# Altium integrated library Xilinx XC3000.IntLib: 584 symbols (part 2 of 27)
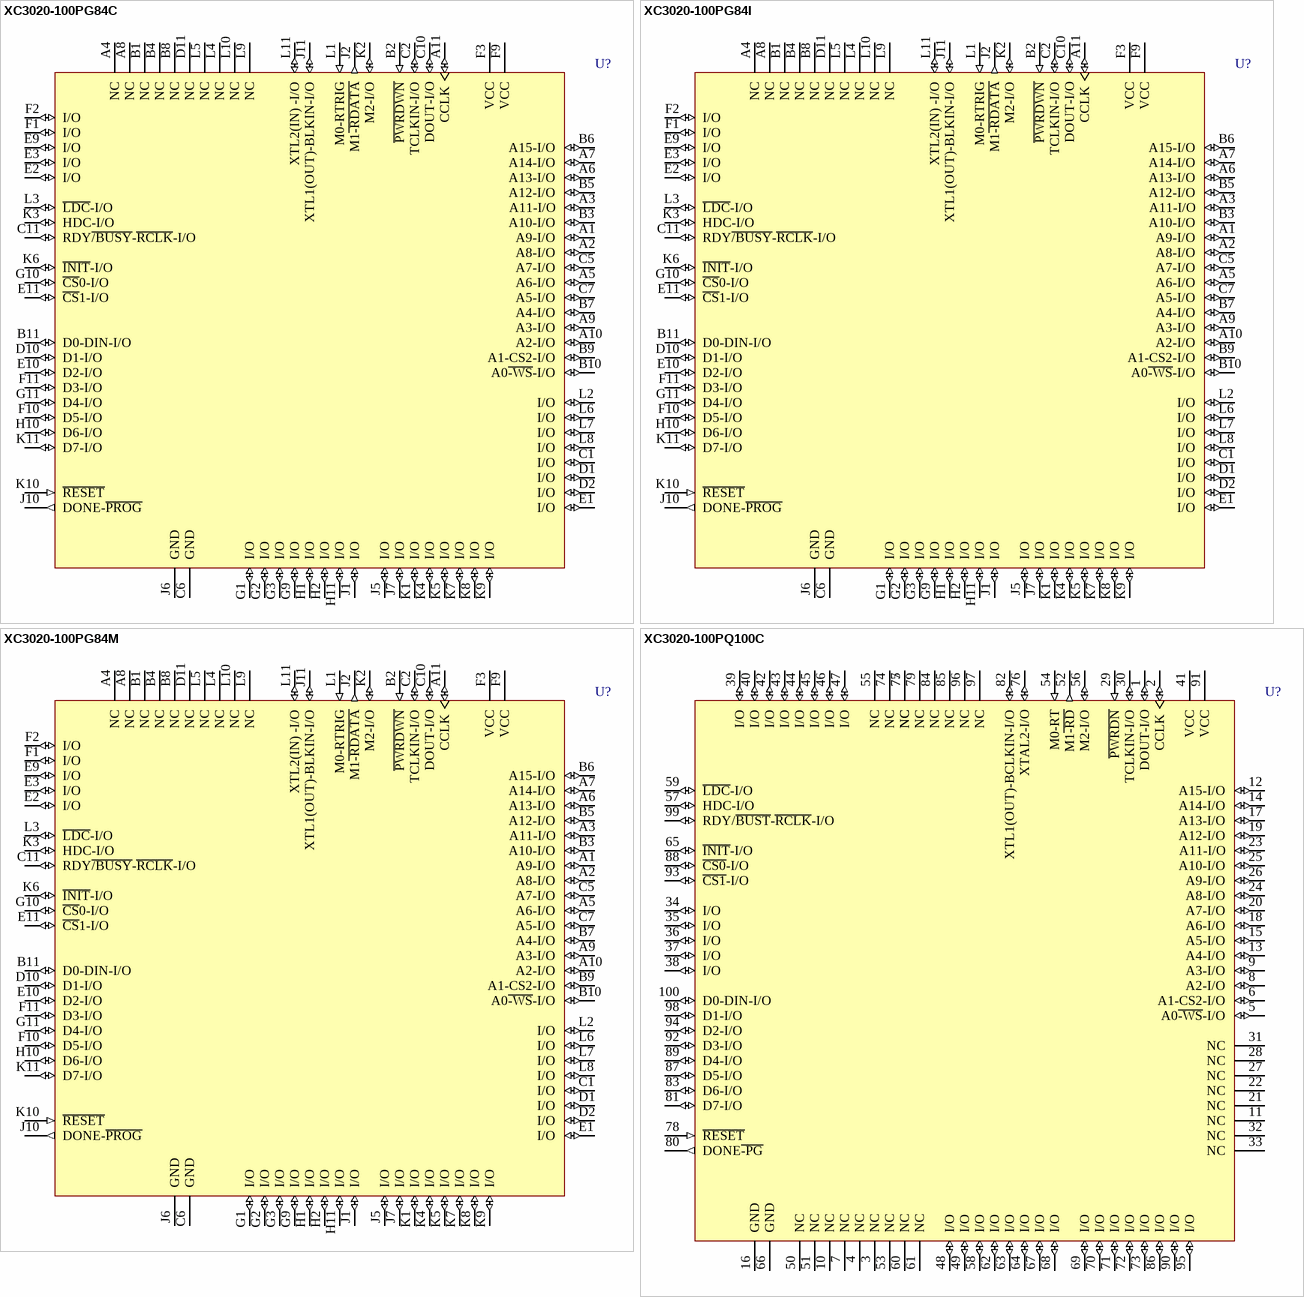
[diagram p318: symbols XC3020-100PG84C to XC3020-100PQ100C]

## XC3020-100PG84C
designator U?
Logic Cell Array with 64 CLBs, with 64 I/O Pins, 84-Pin PGA, Commercial Grade; ComponentAvailability: Not for New Design
footprint PG84 (PGA, 85-Leads, Body 28x28mm, Pitch 2.54mm)
3D model XC3020-PG84 (84-Pin Ceramic Pin Grid Array (PG84))
pins: A1 A9-I/O (io), A2 A8-I/O (io), A3 A11-I/O (io), A4 NC, A5 A6-I/O (io), A6 A13-I/O (io), A7 A14-I/O (io), A8 NC, A9 A3-I/O (io), A10 A2-I/O (io), A11 CCLK (io), B1 NC, B2 ~{PWRDWN} (in), B3 A10-I/O (io), B4 NC, B5 A12-I/O (io), B6 A15-I/O (io), B7 A4-I/O (io), B8 NC, B9 A1-CS2-I/O (io), B10 A0~{-WS}-I/O (io), B11 D0-DIN-I/O (io), C1 I/O (io), C2 TCLKIN-I/O (io), C5 A7-I/O (io), C6 GND (power), C7 A5-I/O (io), C10 DOUT-I/O (io), C11 RDY~{/BUSY}-~{RCLK}-I/O (io), D1 I/O (io), D2 I/O (io), D10 D1-I/O (io), D11 NC, E1 I/O (io), E2 I/O (io), E3 I/O (io), E9 I/O (io), E10 D2-I/O (io), E11 ~{CS}1-I/O (io), F1 I/O (io), F2 I/O (io), F3 VCC (power), F9 VCC (power), F10 D5-I/O (io), F11 D3-I/O (io), G1 I/O (io), G2 I/O (io), G3 I/O (io), G9 I/O (io), G10 ~{CS}0-I/O (io), G11 D4-I/O (io), H1 I/O (io), H2 I/O (io), H10 D6-I/O (io), H11 I/O (io), J1 I/O (io), J2 M1~{-RDATA} (out), J5 I/O (io), J6 GND (power), J7 I/O (io), J10 DONE-~{PROG} (out), J11 XTL1(OUT)-BLKIN-I/O (io), K1 I/O (io), K2 M2-I/O (io), K3 HDC-I/O (io), K4 I/O (io), K5 I/O (io), K6 ~{INIT}-I/O (io), K7 I/O (io), K8 I/O (io), K9 I/O (io), K10 ~{RESET} (in), K11 D7-I/O (io), L1 M0-RTRIG (in), L2 I/O (io), L3 ~{LDC}-I/O (io), L4 NC, L5 NC, L6 I/O (io), L7 I/O (io), L8 I/O (io), L9 NC, L10 NC, L11 XTL2(IN) -I/O (io)

## XC3020-100PG84I
designator U?
Logic Cell Array with 64 CLBs, with 64 I/O Pins, 84-Pin PGA, Industrial Grade; ComponentAvailability: Not for New Design
footprint PG84 (PGA, 85-Leads, Body 28x28mm, Pitch 2.54mm)
3D model XC3020-PG84 (84-Pin Ceramic Pin Grid Array (PG84))
pins: A1 A9-I/O (io), A2 A8-I/O (io), A3 A11-I/O (io), A4 NC, A5 A6-I/O (io), A6 A13-I/O (io), A7 A14-I/O (io), A8 NC, A9 A3-I/O (io), A10 A2-I/O (io), A11 CCLK (io), B1 NC, B2 ~{PWRDWN} (in), B3 A10-I/O (io), B4 NC, B5 A12-I/O (io), B6 A15-I/O (io), B7 A4-I/O (io), B8 NC, B9 A1-CS2-I/O (io), B10 A0~{-WS}-I/O (io), B11 D0-DIN-I/O (io), C1 I/O (io), C2 TCLKIN-I/O (io), C5 A7-I/O (io), C6 GND (power), C7 A5-I/O (io), C10 DOUT-I/O (io), C11 RDY~{/BUSY}-~{RCLK}-I/O (io), D1 I/O (io), D2 I/O (io), D10 D1-I/O (io), D11 NC, E1 I/O (io), E2 I/O (io), E3 I/O (io), E9 I/O (io), E10 D2-I/O (io), E11 ~{CS}1-I/O (io), F1 I/O (io), F2 I/O (io), F3 VCC (power), F9 VCC (power), F10 D5-I/O (io), F11 D3-I/O (io), G1 I/O (io), G2 I/O (io), G3 I/O (io), G9 I/O (io), G10 ~{CS}0-I/O (io), G11 D4-I/O (io), H1 I/O (io), H2 I/O (io), H10 D6-I/O (io), H11 I/O (io), J1 I/O (io), J2 M1~{-RDATA} (out), J5 I/O (io), J6 GND (power), J7 I/O (io), J10 DONE-~{PROG} (out), J11 XTL1(OUT)-BLKIN-I/O (io), K1 I/O (io), K2 M2-I/O (io), K3 HDC-I/O (io), K4 I/O (io), K5 I/O (io), K6 ~{INIT}-I/O (io), K7 I/O (io), K8 I/O (io), K9 I/O (io), K10 ~{RESET} (in), K11 D7-I/O (io), L1 M0-RTRIG (in), L2 I/O (io), L3 ~{LDC}-I/O (io), L4 NC, L5 NC, L6 I/O (io), L7 I/O (io), L8 I/O (io), L9 NC, L10 NC, L11 XTL2(IN) -I/O (io)

## XC3020-100PG84M
designator U?
Logic Cell Array with 64 CLBs, with 64 I/O Pins, 84-Pin PGA, Military Grade; ComponentAvailability: Not for New Design
footprint PG84 (PGA, 85-Leads, Body 28x28mm, Pitch 2.54mm)
3D model XC3020-PG84 (84-Pin Ceramic Pin Grid Array (PG84))
pins: A1 A9-I/O (io), A2 A8-I/O (io), A3 A11-I/O (io), A4 NC, A5 A6-I/O (io), A6 A13-I/O (io), A7 A14-I/O (io), A8 NC, A9 A3-I/O (io), A10 A2-I/O (io), A11 CCLK (io), B1 NC, B2 ~{PWRDWN} (in), B3 A10-I/O (io), B4 NC, B5 A12-I/O (io), B6 A15-I/O (io), B7 A4-I/O (io), B8 NC, B9 A1-CS2-I/O (io), B10 A0~{-WS}-I/O (io), B11 D0-DIN-I/O (io), C1 I/O (io), C2 TCLKIN-I/O (io), C5 A7-I/O (io), C6 GND (power), C7 A5-I/O (io), C10 DOUT-I/O (io), C11 RDY~{/BUSY}-~{RCLK}-I/O (io), D1 I/O (io), D2 I/O (io), D10 D1-I/O (io), D11 NC, E1 I/O (io), E2 I/O (io), E3 I/O (io), E9 I/O (io), E10 D2-I/O (io), E11 ~{CS}1-I/O (io), F1 I/O (io), F2 I/O (io), F3 VCC (power), F9 VCC (power), F10 D5-I/O (io), F11 D3-I/O (io), G1 I/O (io), G2 I/O (io), G3 I/O (io), G9 I/O (io), G10 ~{CS}0-I/O (io), G11 D4-I/O (io), H1 I/O (io), H2 I/O (io), H10 D6-I/O (io), H11 I/O (io), J1 I/O (io), J2 M1~{-RDATA} (out), J5 I/O (io), J6 GND (power), J7 I/O (io), J10 DONE-~{PROG} (out), J11 XTL1(OUT)-BLKIN-I/O (io), K1 I/O (io), K2 M2-I/O (io), K3 HDC-I/O (io), K4 I/O (io), K5 I/O (io), K6 ~{INIT}-I/O (io), K7 I/O (io), K8 I/O (io), K9 I/O (io), K10 ~{RESET} (in), K11 D7-I/O (io), L1 M0-RTRIG (in), L2 I/O (io), L3 ~{LDC}-I/O (io), L4 NC, L5 NC, L6 I/O (io), L7 I/O (io), L8 I/O (io), L9 NC, L10 NC, L11 XTL2(IN) -I/O (io)

## XC3020-100PQ100C
designator U?
Logic Cell Array with 64 CLBs, with 64 I/O Pins, 100-Pin PQFP, Commercial Grade; ComponentAvailability: Not for New Design
footprint PQ100_N (QFP, 100-Leads, Body 20x14mm, Pitch 0.65mm, IPC Medium Density)
footprint PQ100_L (QFP, 100-Leads, Body 20x14mm, Pitch 0.65mm, IPC High Density)
footprint PQ100_M (QFP, 100-Leads, Body 20x14mm, Pitch 0.65mm, IPC Low Density)
3D model XC3020-PQ100 (100-Pin Plastic Quad Flat Pack (PQ100))
pins: 1 DOUT-I/O (io), 2 CCLK (io), 3 NC, 4 NC, 5 A0~{-WS}-I/O (io), 6 A1-CS2-I/O (io), 7 NC, 8 A2-I/O (io), 9 A3-I/O (io), 10 NC, 11 NC, 12 A15-I/O (io), 13 A4-I/O (io), 14 A14-I/O (io), 15 A5-I/O (io), 16 GND (power), 17 A13-I/O (io), 18 A6-I/O (io), 19 A12-I/O (io), 20 A7-I/O (io), 21 NC, 22 NC, 23 A11-I/O (io), 24 A8-I/O (io), 25 A10-I/O (io), 26 A9-I/O (io), 27 NC, 28 NC, 29 ~{PWRDN} (in), 30 TCLKIN-I/O (io), 31 NC, 32 NC, 33 NC, 34 I/O (io), 35 I/O (io), 36 I/O (io), 37 I/O (io), 38 I/O (io), 39 I/O (io), 40 I/O (io), 41 VCC (power), 42 I/O (io), 43 I/O (io), 44 I/O (io), 45 I/O (io), 46 I/O (io), 47 I/O (io), 48 I/O (io), 49 I/O (io), 50 NC, 51 NC, 52 M1~{-RD} (out), 53 NC, 54 M0-RT (in), 55 NC, 56 M2-I/O (io), 57 HDC-I/O (io), 58 I/O (io), 59 ~{LDC}-I/O (io), 60 NC, 61 NC, 62 I/O (io), 63 I/O (io), 64 I/O (io), 65 ~{INIT}-I/O (io), 66 GND (power), 67 I/O (io), 68 I/O (io), 69 I/O (io), 70 I/O (io), 71 I/O (io), 72 I/O (io), 73 I/O (io), 74 NC, 75 NC, 76 XTAL2-I/O (io), 77 NC, 78 ~{RESET} (in), 79 NC, 80 DONE~{-PG} (out), 81 D7-I/O (io), 82 XTL1(OUT)-BCLKIN-I/O (io), 83 D6-I/O (io), 84 NC, 85 NC, 86 I/O (io), 87 D5-I/O (io), 88 ~{CS0}-I/O (io), 89 D4-I/O (io), 90 I/O (io), 91 VCC (power), 92 D3-I/O (io), 93 ~{CS1}-I/O (io), 94 D2-I/O (io), 95 I/O (io), 96 NC, 97 NC, 98 D1-I/O (io), 99 RDY/~{BUST}-~{RCLK}-I/O (io), 100 D0-DIN-I/O (io)

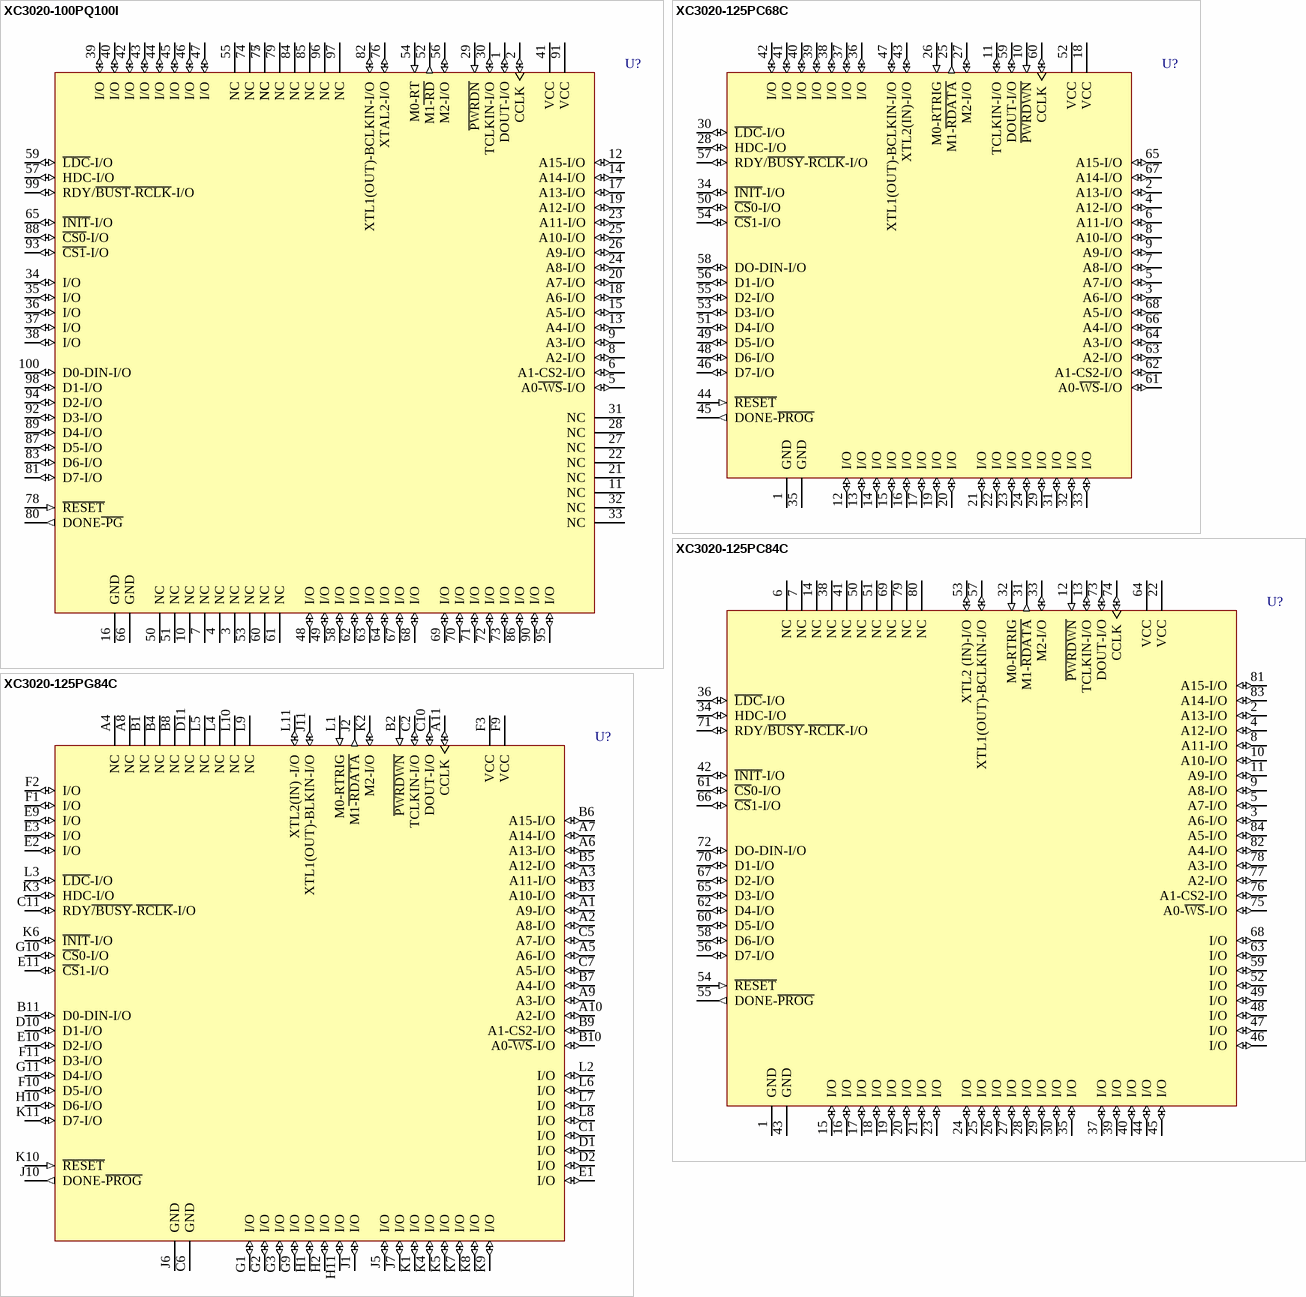
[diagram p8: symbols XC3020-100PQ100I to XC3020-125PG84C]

## XC3020-100PQ100I
designator U?
Logic Cell Array with 64 CLBs, with 64 I/O Pins, 100-Pin PQFP, Industrial Grade; ComponentAvailability: Not for New Design
footprint PQ100_N (QFP, 100-Leads, Body 20x14mm, Pitch 0.65mm, IPC Medium Density)
footprint PQ100_L (QFP, 100-Leads, Body 20x14mm, Pitch 0.65mm, IPC High Density)
footprint PQ100_M (QFP, 100-Leads, Body 20x14mm, Pitch 0.65mm, IPC Low Density)
3D model XC3020-PQ100 (100-Pin Plastic Quad Flat Pack (PQ100))
pins: 1 DOUT-I/O (io), 2 CCLK (io), 3 NC, 4 NC, 5 A0~{-WS}-I/O (io), 6 A1-CS2-I/O (io), 7 NC, 8 A2-I/O (io), 9 A3-I/O (io), 10 NC, 11 NC, 12 A15-I/O (io), 13 A4-I/O (io), 14 A14-I/O (io), 15 A5-I/O (io), 16 GND (power), 17 A13-I/O (io), 18 A6-I/O (io), 19 A12-I/O (io), 20 A7-I/O (io), 21 NC, 22 NC, 23 A11-I/O (io), 24 A8-I/O (io), 25 A10-I/O (io), 26 A9-I/O (io), 27 NC, 28 NC, 29 ~{PWRDN} (in), 30 TCLKIN-I/O (io), 31 NC, 32 NC, 33 NC, 34 I/O (io), 35 I/O (io), 36 I/O (io), 37 I/O (io), 38 I/O (io), 39 I/O (io), 40 I/O (io), 41 VCC (power), 42 I/O (io), 43 I/O (io), 44 I/O (io), 45 I/O (io), 46 I/O (io), 47 I/O (io), 48 I/O (io), 49 I/O (io), 50 NC, 51 NC, 52 M1~{-RD} (out), 53 NC, 54 M0-RT (in), 55 NC, 56 M2-I/O (io), 57 HDC-I/O (io), 58 I/O (io), 59 ~{LDC}-I/O (io), 60 NC, 61 NC, 62 I/O (io), 63 I/O (io), 64 I/O (io), 65 ~{INIT}-I/O (io), 66 GND (power), 67 I/O (io), 68 I/O (io), 69 I/O (io), 70 I/O (io), 71 I/O (io), 72 I/O (io), 73 I/O (io), 74 NC, 75 NC, 76 XTAL2-I/O (io), 77 NC, 78 ~{RESET} (in), 79 NC, 80 DONE~{-PG} (out), 81 D7-I/O (io), 82 XTL1(OUT)-BCLKIN-I/O (io), 83 D6-I/O (io), 84 NC, 85 NC, 86 I/O (io), 87 D5-I/O (io), 88 ~{CS0}-I/O (io), 89 D4-I/O (io), 90 I/O (io), 91 VCC (power), 92 D3-I/O (io), 93 ~{CS1}-I/O (io), 94 D2-I/O (io), 95 I/O (io), 96 NC, 97 NC, 98 D1-I/O (io), 99 RDY/~{BUST}-~{RCLK}-I/O (io), 100 D0-DIN-I/O (io)

## XC3020-125PC68C
designator U?
Logic Cell Array with 64 CLBs, with 58 I/O Pins, 68-Pin PLCC, Commercial Grade; ComponentAvailability: Not for New Design
footprint PC68_N (Leaded Chip Carrier, 68-Leads, Body 24x24mm, Pitch 1.27mm, IPC Medium Density)
footprint PC68_L (Leaded Chip Carrier, 68-Leads, Body 24x24mm, Pitch 1.27mm, IPC High Density)
footprint PC68_M (Leaded Chip Carrier, 68-Leads, Body 24x24mm, Pitch 1.27mm, IPC Low Density)
3D model XC3020-PC68 (68-Pin Plastic Leaded Chip Carrier (PC68))
pins: 1 GND (power), 2 A13-I/O (io), 3 A6-I/O (io), 4 A12-I/O (io), 5 A7-I/O (io), 6 A11-I/O (io), 7 A8-I/O (io), 8 A10-I/O (io), 9 A9-I/O (io), 10 ~{PWRDWN} (in), 11 TCLKIN-I/O (io), 12 I/O (io), 13 I/O (io), 14 I/O (io), 15 I/O (io), 16 I/O (io), 17 I/O (io), 18 VCC (power), 19 I/O (io), 20 I/O (io), 21 I/O (io), 22 I/O (io), 23 I/O (io), 24 I/O (io), 25 M1-~{RDATA} (out), 26 M0-RTRIG (in), 27 M2-I/O (io), 28 HDC-I/O (io), 29 I/O (io), 30 ~{LDC}-I/O (io), 31 I/O (io), 32 I/O (io), 33 I/O (io), 34 ~{INIT}-I/O (io), 35 GND (power), 36 I/O (io), 37 I/O (io), 38 I/O (io), 39 I/O (io), 40 I/O (io), 41 I/O (io), 42 I/O (io), 43 XTL2(IN)-I/O (io), 44 ~{RESET} (in), 45 DONE-~{PROG} (out), 46 D7-I/O (io), 47 XTL1(OUT)-BCLKIN-I/O (io), 48 D6-I/O (io), 49 D5-I/O (io), 50 ~{CS}0-I/O (io), 51 D4-I/O (io), 52 VCC (power), 53 D3-I/O (io), 54 ~{CS}1-I/O (io), 55 D2-I/O (io), 56 D1-I/O (io), 57 RDY/~{BUSY}-~{RCLK}-I/O (io), 58 DO-DIN-I/O (io), 59 DOUT-I/O (io), 60 CCLK (io), 61 A0-~{WS}-I/O (io), 62 A1-CS2-I/O (io), 63 A2-I/O (io), 64 A3-I/O (io), 65 A15-I/O (io), 66 A4-I/O (io), 67 A14-I/O (io), 68 A5-I/O (io)

## XC3020-125PC84C
designator U?
Logic Cell Array with 64 CLBs, with 64 I/O Pins, 84-Pin PLCC, Commercial Grade; ComponentAvailability: Not for New Design
footprint PC84_N (Leaded Chip Carrier, 84-Leads, Body 29.3x29.3mm, Pitch 1.27mm, IPC Medium Density)
footprint PC84_L (Leaded Chip Carrier, 84-Leads, Body 29.3x29.3mm, Pitch 1.27mm, IPC High Density)
footprint PC84_M (Leaded Chip Carrier, 84-Leads, Body 29.3x29.3mm, Pitch 1.27mm, IPC Low Density)
3D model XC3020-PC84 (84-Pin Plastic Leaded Chip Carrier (PC84))
pins: 1 GND (power), 2 A13-I/O (io), 3 A6-I/O (io), 4 A12-I/O (io), 5 A7-I/O (io), 6 NC, 7 NC, 8 A11-I/O (io), 9 A8-I/O (io), 10 A10-I/O (io), 11 A9-I/O (io), 12 ~{PWRDWN} (in), 13 TCLKIN-I/O (io), 14 NC, 15 I/O (io), 16 I/O (io), 17 I/O (io), 18 I/O (io), 19 I/O (io), 20 I/O (io), 21 I/O (io), 22 VCC (power), 23 I/O (io), 24 I/O (io), 25 I/O (io), 26 I/O (io), 27 I/O (io), 28 I/O (io), 29 I/O (io), 30 I/O (io), 31 M1-~{RDATA} (out), 32 M0-RTRIG (in), 33 M2-I/O (io), 34 HDC-I/O (io), 35 I/O (io), 36 ~{LDC}-I/O (io), 37 I/O (io), 38 NC, 39 I/O (io), 40 I/O (io), 41 NC, 42 ~{INIT}-I/O (io), 43 GND (power), 44 I/O (io), 45 I/O (io), 46 I/O (io), 47 I/O (io), 48 I/O (io), 49 I/O (io), 50 NC, 51 NC, 52 I/O (io), 53 XTL2 (IN)-I/O (io), 54 ~{RESET} (in), 55 DONE-~{PROG} (out), 56 D7-I/O (io), 57 XTL1(OUT)-BCLKIN-I/O (io), 58 D6-I/O (io), 59 I/O (io), 60 D5-I/O (io), 61 ~{CS}0-I/O (io), 62 D4-I/O (io), 63 I/O (io), 64 VCC (power), 65 D3-I/O (io), 66 ~{CS}1-I/O (io), 67 D2-I/O (io), 68 I/O (io), 69 NC, 70 D1-I/O (io), 71 RDY/~{BUSY}-~{RCLK}-I/O (io), 72 DO-DIN-I/O (io), 73 DOUT-I/O (io), 74 CCLK (io), 75 A0-~{WS}-I/O (io), 76 A1-CS2-I/O (io), 77 A2-I/O (io), 78 A3-I/O (io), 79 NC, 80 NC, 81 A15-I/O (io), 82 A4-I/O (io), 83 A14-I/O (io), 84 A5-I/O (io)

## XC3020-125PG84C
designator U?
Logic Cell Array with 64 CLBs, with 64 I/O Pins, 84-Pin PGA, Commercial Grade; ComponentAvailability: Not for New Design
footprint PG84 (PGA, 85-Leads, Body 28x28mm, Pitch 2.54mm)
3D model XC3020-PG84 (84-Pin Ceramic Pin Grid Array (PG84))
pins: A1 A9-I/O (io), A2 A8-I/O (io), A3 A11-I/O (io), A4 NC, A5 A6-I/O (io), A6 A13-I/O (io), A7 A14-I/O (io), A8 NC, A9 A3-I/O (io), A10 A2-I/O (io), A11 CCLK (io), B1 NC, B2 ~{PWRDWN} (in), B3 A10-I/O (io), B4 NC, B5 A12-I/O (io), B6 A15-I/O (io), B7 A4-I/O (io), B8 NC, B9 A1-CS2-I/O (io), B10 A0~{-WS}-I/O (io), B11 D0-DIN-I/O (io), C1 I/O (io), C2 TCLKIN-I/O (io), C5 A7-I/O (io), C6 GND (power), C7 A5-I/O (io), C10 DOUT-I/O (io), C11 RDY~{/BUSY}-~{RCLK}-I/O (io), D1 I/O (io), D2 I/O (io), D10 D1-I/O (io), D11 NC, E1 I/O (io), E2 I/O (io), E3 I/O (io), E9 I/O (io), E10 D2-I/O (io), E11 ~{CS}1-I/O (io), F1 I/O (io), F2 I/O (io), F3 VCC (power), F9 VCC (power), F10 D5-I/O (io), F11 D3-I/O (io), G1 I/O (io), G2 I/O (io), G3 I/O (io), G9 I/O (io), G10 ~{CS}0-I/O (io), G11 D4-I/O (io), H1 I/O (io), H2 I/O (io), H10 D6-I/O (io), H11 I/O (io), J1 I/O (io), J2 M1~{-RDATA} (out), J5 I/O (io), J6 GND (power), J7 I/O (io), J10 DONE-~{PROG} (out), J11 XTL1(OUT)-BLKIN-I/O (io), K1 I/O (io), K2 M2-I/O (io), K3 HDC-I/O (io), K4 I/O (io), K5 I/O (io), K6 ~{INIT}-I/O (io), K7 I/O (io), K8 I/O (io), K9 I/O (io), K10 ~{RESET} (in), K11 D7-I/O (io), L1 M0-RTRIG (in), L2 I/O (io), L3 ~{LDC}-I/O (io), L4 NC, L5 NC, L6 I/O (io), L7 I/O (io), L8 I/O (io), L9 NC, L10 NC, L11 XTL2(IN) -I/O (io)

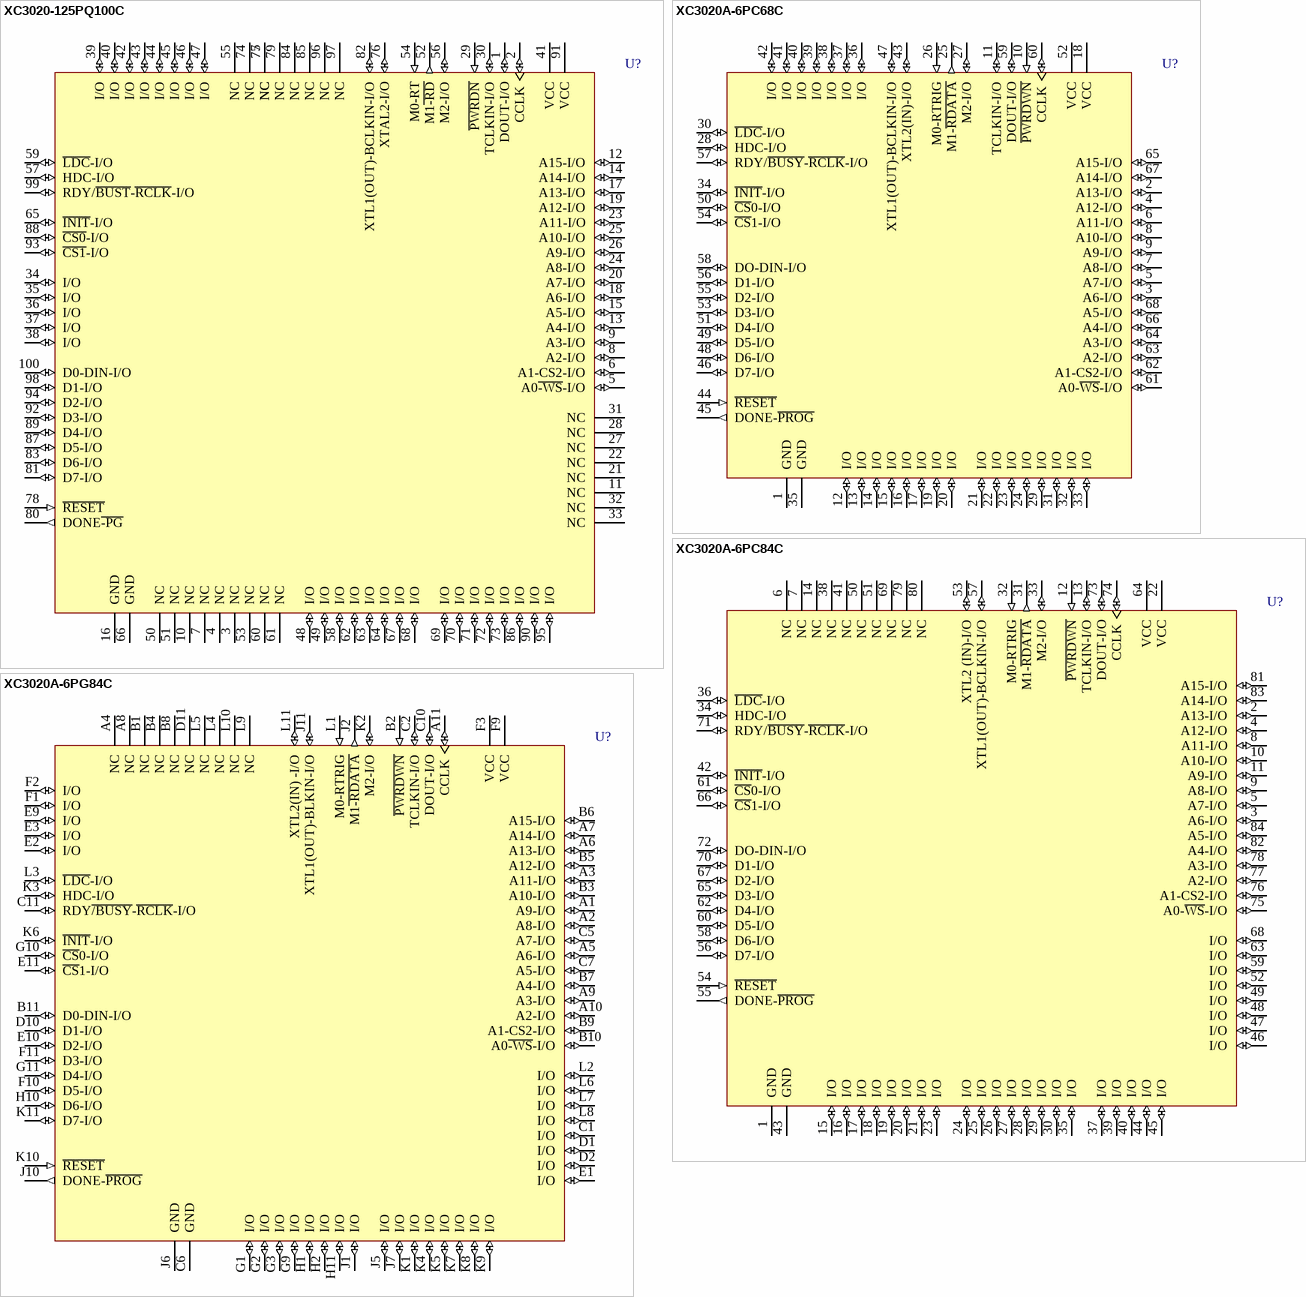
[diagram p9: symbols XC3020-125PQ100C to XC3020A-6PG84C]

## XC3020-125PQ100C
designator U?
Logic Cell Array with 64 CLBs, with 64 I/O Pins, 100-Pin PQFP, Commercial Grade; ComponentAvailability: Not for New Design
footprint PQ100_N (QFP, 100-Leads, Body 20x14mm, Pitch 0.65mm, IPC Medium Density)
footprint PQ100_L (QFP, 100-Leads, Body 20x14mm, Pitch 0.65mm, IPC High Density)
footprint PQ100_M (QFP, 100-Leads, Body 20x14mm, Pitch 0.65mm, IPC Low Density)
3D model XC3020-PQ100 (100-Pin Plastic Quad Flat Pack (PQ100))
pins: 1 DOUT-I/O (io), 2 CCLK (io), 3 NC, 4 NC, 5 A0~{-WS}-I/O (io), 6 A1-CS2-I/O (io), 7 NC, 8 A2-I/O (io), 9 A3-I/O (io), 10 NC, 11 NC, 12 A15-I/O (io), 13 A4-I/O (io), 14 A14-I/O (io), 15 A5-I/O (io), 16 GND (power), 17 A13-I/O (io), 18 A6-I/O (io), 19 A12-I/O (io), 20 A7-I/O (io), 21 NC, 22 NC, 23 A11-I/O (io), 24 A8-I/O (io), 25 A10-I/O (io), 26 A9-I/O (io), 27 NC, 28 NC, 29 ~{PWRDN} (in), 30 TCLKIN-I/O (io), 31 NC, 32 NC, 33 NC, 34 I/O (io), 35 I/O (io), 36 I/O (io), 37 I/O (io), 38 I/O (io), 39 I/O (io), 40 I/O (io), 41 VCC (power), 42 I/O (io), 43 I/O (io), 44 I/O (io), 45 I/O (io), 46 I/O (io), 47 I/O (io), 48 I/O (io), 49 I/O (io), 50 NC, 51 NC, 52 M1~{-RD} (out), 53 NC, 54 M0-RT (in), 55 NC, 56 M2-I/O (io), 57 HDC-I/O (io), 58 I/O (io), 59 ~{LDC}-I/O (io), 60 NC, 61 NC, 62 I/O (io), 63 I/O (io), 64 I/O (io), 65 ~{INIT}-I/O (io), 66 GND (power), 67 I/O (io), 68 I/O (io), 69 I/O (io), 70 I/O (io), 71 I/O (io), 72 I/O (io), 73 I/O (io), 74 NC, 75 NC, 76 XTAL2-I/O (io), 77 NC, 78 ~{RESET} (in), 79 NC, 80 DONE~{-PG} (out), 81 D7-I/O (io), 82 XTL1(OUT)-BCLKIN-I/O (io), 83 D6-I/O (io), 84 NC, 85 NC, 86 I/O (io), 87 D5-I/O (io), 88 ~{CS0}-I/O (io), 89 D4-I/O (io), 90 I/O (io), 91 VCC (power), 92 D3-I/O (io), 93 ~{CS1}-I/O (io), 94 D2-I/O (io), 95 I/O (io), 96 NC, 97 NC, 98 D1-I/O (io), 99 RDY/~{BUST}-~{RCLK}-I/O (io), 100 D0-DIN-I/O (io)

## XC3020A-6PC68C
designator U?
Logic Cell Array with 64 CLBs, with 58 I/O Pins, 68-Pin PLCC, Commercial Grade; ComponentAvailability: Not for New Design
footprint PC68_N (Leaded Chip Carrier, 68-Leads, Body 24x24mm, Pitch 1.27mm, IPC Medium Density)
footprint PC68_L (Leaded Chip Carrier, 68-Leads, Body 24x24mm, Pitch 1.27mm, IPC High Density)
footprint PC68_M (Leaded Chip Carrier, 68-Leads, Body 24x24mm, Pitch 1.27mm, IPC Low Density)
3D model XC3020A-PC68 (68-Pin Plastic Leaded Chip Carrier (PC68))
pins: 1 GND (power), 2 A13-I/O (io), 3 A6-I/O (io), 4 A12-I/O (io), 5 A7-I/O (io), 6 A11-I/O (io), 7 A8-I/O (io), 8 A10-I/O (io), 9 A9-I/O (io), 10 ~{PWRDWN} (in), 11 TCLKIN-I/O (io), 12 I/O (io), 13 I/O (io), 14 I/O (io), 15 I/O (io), 16 I/O (io), 17 I/O (io), 18 VCC (power), 19 I/O (io), 20 I/O (io), 21 I/O (io), 22 I/O (io), 23 I/O (io), 24 I/O (io), 25 M1-~{RDATA} (out), 26 M0-RTRIG (in), 27 M2-I/O (io), 28 HDC-I/O (io), 29 I/O (io), 30 ~{LDC}-I/O (io), 31 I/O (io), 32 I/O (io), 33 I/O (io), 34 ~{INIT}-I/O (io), 35 GND (power), 36 I/O (io), 37 I/O (io), 38 I/O (io), 39 I/O (io), 40 I/O (io), 41 I/O (io), 42 I/O (io), 43 XTL2(IN)-I/O (io), 44 ~{RESET} (in), 45 DONE-~{PROG} (out), 46 D7-I/O (io), 47 XTL1(OUT)-BCLKIN-I/O (io), 48 D6-I/O (io), 49 D5-I/O (io), 50 ~{CS}0-I/O (io), 51 D4-I/O (io), 52 VCC (power), 53 D3-I/O (io), 54 ~{CS}1-I/O (io), 55 D2-I/O (io), 56 D1-I/O (io), 57 RDY/~{BUSY}-~{RCLK}-I/O (io), 58 DO-DIN-I/O (io), 59 DOUT-I/O (io), 60 CCLK (io), 61 A0-~{WS}-I/O (io), 62 A1-CS2-I/O (io), 63 A2-I/O (io), 64 A3-I/O (io), 65 A15-I/O (io), 66 A4-I/O (io), 67 A14-I/O (io), 68 A5-I/O (io)

## XC3020A-6PC84C
designator U?
Logic Cell Array with 64 CLBs, with 64 I/O Pins, 84-Pin PLCC, Commercial Grade; ComponentAvailability: Not for New Design
footprint PC84_N (Leaded Chip Carrier, 84-Leads, Body 29.3x29.3mm, Pitch 1.27mm, IPC Medium Density)
footprint PC84_L (Leaded Chip Carrier, 84-Leads, Body 29.3x29.3mm, Pitch 1.27mm, IPC High Density)
footprint PC84_M (Leaded Chip Carrier, 84-Leads, Body 29.3x29.3mm, Pitch 1.27mm, IPC Low Density)
3D model XC3020A-PC84 (84-Pin Plastic Leaded Chip Carrier (PC84))
pins: 1 GND (power), 2 A13-I/O (io), 3 A6-I/O (io), 4 A12-I/O (io), 5 A7-I/O (io), 6 NC, 7 NC, 8 A11-I/O (io), 9 A8-I/O (io), 10 A10-I/O (io), 11 A9-I/O (io), 12 ~{PWRDWN} (in), 13 TCLKIN-I/O (io), 14 NC, 15 I/O (io), 16 I/O (io), 17 I/O (io), 18 I/O (io), 19 I/O (io), 20 I/O (io), 21 I/O (io), 22 VCC (power), 23 I/O (io), 24 I/O (io), 25 I/O (io), 26 I/O (io), 27 I/O (io), 28 I/O (io), 29 I/O (io), 30 I/O (io), 31 M1-~{RDATA} (out), 32 M0-RTRIG (in), 33 M2-I/O (io), 34 HDC-I/O (io), 35 I/O (io), 36 ~{LDC}-I/O (io), 37 I/O (io), 38 NC, 39 I/O (io), 40 I/O (io), 41 NC, 42 ~{INIT}-I/O (io), 43 GND (power), 44 I/O (io), 45 I/O (io), 46 I/O (io), 47 I/O (io), 48 I/O (io), 49 I/O (io), 50 NC, 51 NC, 52 I/O (io), 53 XTL2 (IN)-I/O (io), 54 ~{RESET} (in), 55 DONE-~{PROG} (out), 56 D7-I/O (io), 57 XTL1(OUT)-BCLKIN-I/O (io), 58 D6-I/O (io), 59 I/O (io), 60 D5-I/O (io), 61 ~{CS}0-I/O (io), 62 D4-I/O (io), 63 I/O (io), 64 VCC (power), 65 D3-I/O (io), 66 ~{CS}1-I/O (io), 67 D2-I/O (io), 68 I/O (io), 69 NC, 70 D1-I/O (io), 71 RDY/~{BUSY}-~{RCLK}-I/O (io), 72 DO-DIN-I/O (io), 73 DOUT-I/O (io), 74 CCLK (io), 75 A0-~{WS}-I/O (io), 76 A1-CS2-I/O (io), 77 A2-I/O (io), 78 A3-I/O (io), 79 NC, 80 NC, 81 A15-I/O (io), 82 A4-I/O (io), 83 A14-I/O (io), 84 A5-I/O (io)

## XC3020A-6PG84C
designator U?
Logic Cell Array with 64 CLBs, with 64 I/O Pins, 84-Pin PGA, Commercial Grade; ComponentAvailability: Not for New Design
footprint PG84 (PGA, 85-Leads, Body 28x28mm, Pitch 2.54mm)
3D model XC3020A-PG84 (84-Pin Ceramic Pin Grid Array (PG84))
pins: A1 A9-I/O (io), A2 A8-I/O (io), A3 A11-I/O (io), A4 NC, A5 A6-I/O (io), A6 A13-I/O (io), A7 A14-I/O (io), A8 NC, A9 A3-I/O (io), A10 A2-I/O (io), A11 CCLK (io), B1 NC, B2 ~{PWRDWN} (in), B3 A10-I/O (io), B4 NC, B5 A12-I/O (io), B6 A15-I/O (io), B7 A4-I/O (io), B8 NC, B9 A1-CS2-I/O (io), B10 A0~{-WS}-I/O (io), B11 D0-DIN-I/O (io), C1 I/O (io), C2 TCLKIN-I/O (io), C5 A7-I/O (io), C6 GND (power), C7 A5-I/O (io), C10 DOUT-I/O (io), C11 RDY~{/BUSY}-~{RCLK}-I/O (io), D1 I/O (io), D2 I/O (io), D10 D1-I/O (io), D11 NC, E1 I/O (io), E2 I/O (io), E3 I/O (io), E9 I/O (io), E10 D2-I/O (io), E11 ~{CS}1-I/O (io), F1 I/O (io), F2 I/O (io), F3 VCC (power), F9 VCC (power), F10 D5-I/O (io), F11 D3-I/O (io), G1 I/O (io), G2 I/O (io), G3 I/O (io), G9 I/O (io), G10 ~{CS}0-I/O (io), G11 D4-I/O (io), H1 I/O (io), H2 I/O (io), H10 D6-I/O (io), H11 I/O (io), J1 I/O (io), J2 M1~{-RDATA} (out), J5 I/O (io), J6 GND (power), J7 I/O (io), J10 DONE-~{PROG} (out), J11 XTL1(OUT)-BLKIN-I/O (io), K1 I/O (io), K2 M2-I/O (io), K3 HDC-I/O (io), K4 I/O (io), K5 I/O (io), K6 ~{INIT}-I/O (io), K7 I/O (io), K8 I/O (io), K9 I/O (io), K10 ~{RESET} (in), K11 D7-I/O (io), L1 M0-RTRIG (in), L2 I/O (io), L3 ~{LDC}-I/O (io), L4 NC, L5 NC, L6 I/O (io), L7 I/O (io), L8 I/O (io), L9 NC, L10 NC, L11 XTL2(IN) -I/O (io)

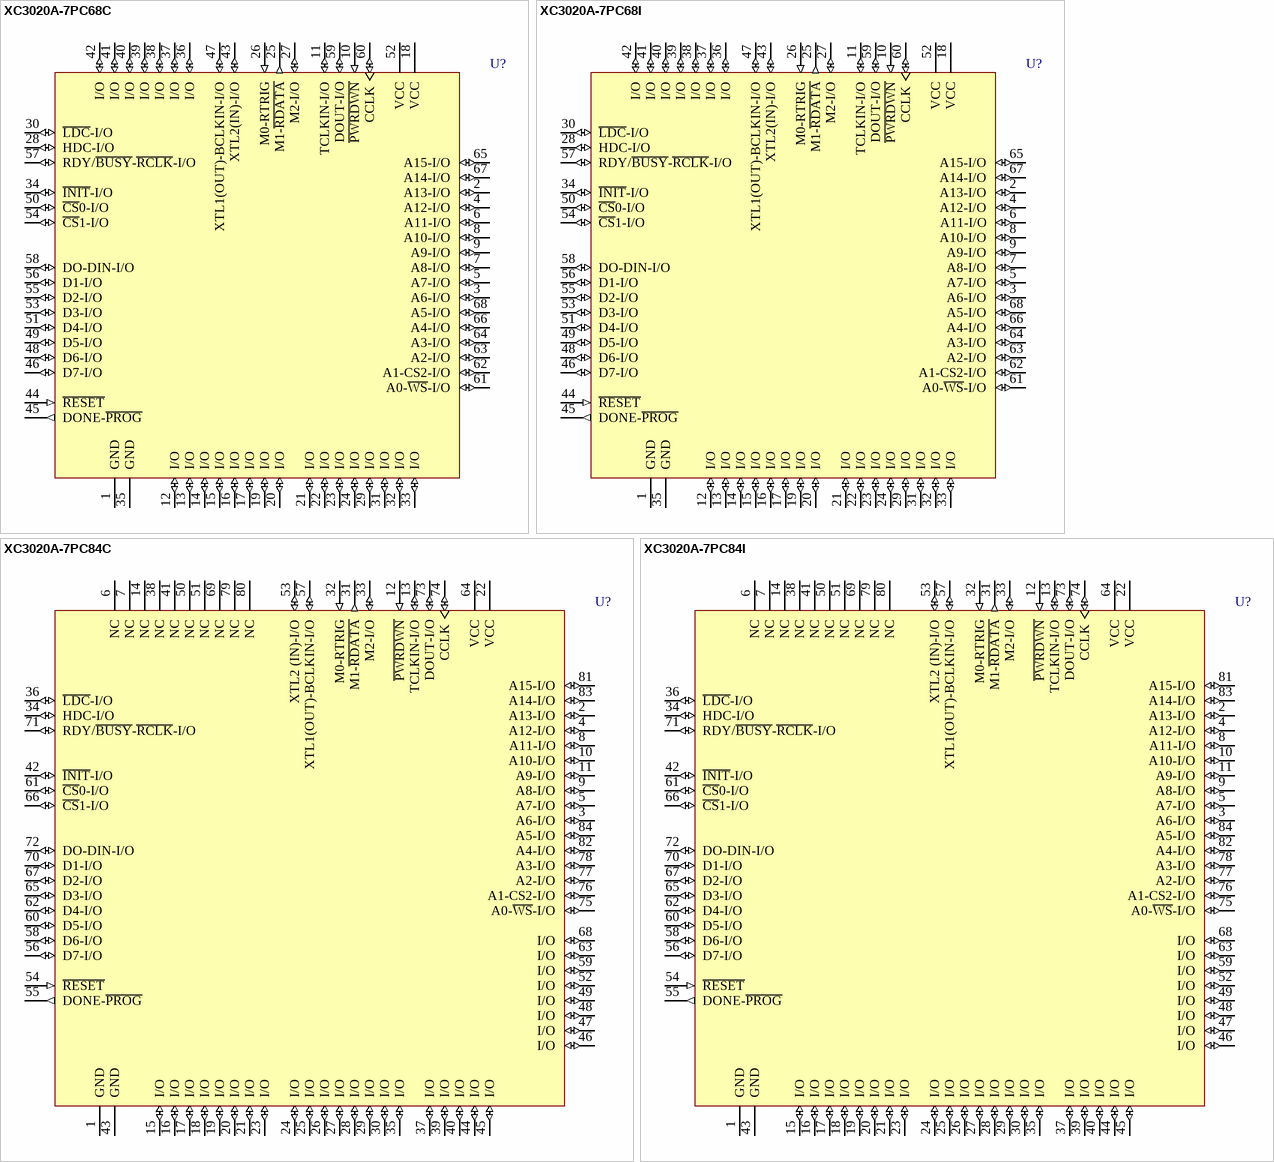
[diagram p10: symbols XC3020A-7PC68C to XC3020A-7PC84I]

## XC3020A-7PC68C
designator U?
Logic Cell Array with 64 CLBs, with 58 I/O Pins, 68-Pin PLCC, Commercial Grade; ComponentAvailability: Not for New Design
footprint PC68_N (Leaded Chip Carrier, 68-Leads, Body 24x24mm, Pitch 1.27mm, IPC Medium Density)
footprint PC68_L (Leaded Chip Carrier, 68-Leads, Body 24x24mm, Pitch 1.27mm, IPC High Density)
footprint PC68_M (Leaded Chip Carrier, 68-Leads, Body 24x24mm, Pitch 1.27mm, IPC Low Density)
3D model XC3020A-PC68 (68-Pin Plastic Leaded Chip Carrier (PC68))
pins: 1 GND (power), 2 A13-I/O (io), 3 A6-I/O (io), 4 A12-I/O (io), 5 A7-I/O (io), 6 A11-I/O (io), 7 A8-I/O (io), 8 A10-I/O (io), 9 A9-I/O (io), 10 ~{PWRDWN} (in), 11 TCLKIN-I/O (io), 12 I/O (io), 13 I/O (io), 14 I/O (io), 15 I/O (io), 16 I/O (io), 17 I/O (io), 18 VCC (power), 19 I/O (io), 20 I/O (io), 21 I/O (io), 22 I/O (io), 23 I/O (io), 24 I/O (io), 25 M1-~{RDATA} (out), 26 M0-RTRIG (in), 27 M2-I/O (io), 28 HDC-I/O (io), 29 I/O (io), 30 ~{LDC}-I/O (io), 31 I/O (io), 32 I/O (io), 33 I/O (io), 34 ~{INIT}-I/O (io), 35 GND (power), 36 I/O (io), 37 I/O (io), 38 I/O (io), 39 I/O (io), 40 I/O (io), 41 I/O (io), 42 I/O (io), 43 XTL2(IN)-I/O (io), 44 ~{RESET} (in), 45 DONE-~{PROG} (out), 46 D7-I/O (io), 47 XTL1(OUT)-BCLKIN-I/O (io), 48 D6-I/O (io), 49 D5-I/O (io), 50 ~{CS}0-I/O (io), 51 D4-I/O (io), 52 VCC (power), 53 D3-I/O (io), 54 ~{CS}1-I/O (io), 55 D2-I/O (io), 56 D1-I/O (io), 57 RDY/~{BUSY}-~{RCLK}-I/O (io), 58 DO-DIN-I/O (io), 59 DOUT-I/O (io), 60 CCLK (io), 61 A0-~{WS}-I/O (io), 62 A1-CS2-I/O (io), 63 A2-I/O (io), 64 A3-I/O (io), 65 A15-I/O (io), 66 A4-I/O (io), 67 A14-I/O (io), 68 A5-I/O (io)

## XC3020A-7PC68I
designator U?
Logic Cell Array with 64 CLBs, with 58 I/O Pins, 68-Pin PLCC, Industrial Grade; ComponentAvailability: Not for New Design
footprint PC68_N (Leaded Chip Carrier, 68-Leads, Body 24x24mm, Pitch 1.27mm, IPC Medium Density)
footprint PC68_L (Leaded Chip Carrier, 68-Leads, Body 24x24mm, Pitch 1.27mm, IPC High Density)
footprint PC68_M (Leaded Chip Carrier, 68-Leads, Body 24x24mm, Pitch 1.27mm, IPC Low Density)
3D model XC3020A-PC68 (68-Pin Plastic Leaded Chip Carrier (PC68))
pins: 1 GND (power), 2 A13-I/O (io), 3 A6-I/O (io), 4 A12-I/O (io), 5 A7-I/O (io), 6 A11-I/O (io), 7 A8-I/O (io), 8 A10-I/O (io), 9 A9-I/O (io), 10 ~{PWRDWN} (in), 11 TCLKIN-I/O (io), 12 I/O (io), 13 I/O (io), 14 I/O (io), 15 I/O (io), 16 I/O (io), 17 I/O (io), 18 VCC (power), 19 I/O (io), 20 I/O (io), 21 I/O (io), 22 I/O (io), 23 I/O (io), 24 I/O (io), 25 M1-~{RDATA} (out), 26 M0-RTRIG (in), 27 M2-I/O (io), 28 HDC-I/O (io), 29 I/O (io), 30 ~{LDC}-I/O (io), 31 I/O (io), 32 I/O (io), 33 I/O (io), 34 ~{INIT}-I/O (io), 35 GND (power), 36 I/O (io), 37 I/O (io), 38 I/O (io), 39 I/O (io), 40 I/O (io), 41 I/O (io), 42 I/O (io), 43 XTL2(IN)-I/O (io), 44 ~{RESET} (in), 45 DONE-~{PROG} (out), 46 D7-I/O (io), 47 XTL1(OUT)-BCLKIN-I/O (io), 48 D6-I/O (io), 49 D5-I/O (io), 50 ~{CS}0-I/O (io), 51 D4-I/O (io), 52 VCC (power), 53 D3-I/O (io), 54 ~{CS}1-I/O (io), 55 D2-I/O (io), 56 D1-I/O (io), 57 RDY/~{BUSY}-~{RCLK}-I/O (io), 58 DO-DIN-I/O (io), 59 DOUT-I/O (io), 60 CCLK (io), 61 A0-~{WS}-I/O (io), 62 A1-CS2-I/O (io), 63 A2-I/O (io), 64 A3-I/O (io), 65 A15-I/O (io), 66 A4-I/O (io), 67 A14-I/O (io), 68 A5-I/O (io)

## XC3020A-7PC84C
designator U?
Logic Cell Array with 64 CLBs, with 64 I/O Pins, 84-Pin PLCC, Commercial Grade; ComponentAvailability: Not for New Design
footprint PC84_N (Leaded Chip Carrier, 84-Leads, Body 29.3x29.3mm, Pitch 1.27mm, IPC Medium Density)
footprint PC84_L (Leaded Chip Carrier, 84-Leads, Body 29.3x29.3mm, Pitch 1.27mm, IPC High Density)
footprint PC84_M (Leaded Chip Carrier, 84-Leads, Body 29.3x29.3mm, Pitch 1.27mm, IPC Low Density)
3D model XC3020A-PC84 (84-Pin Plastic Leaded Chip Carrier (PC84))
pins: 1 GND (power), 2 A13-I/O (io), 3 A6-I/O (io), 4 A12-I/O (io), 5 A7-I/O (io), 6 NC, 7 NC, 8 A11-I/O (io), 9 A8-I/O (io), 10 A10-I/O (io), 11 A9-I/O (io), 12 ~{PWRDWN} (in), 13 TCLKIN-I/O (io), 14 NC, 15 I/O (io), 16 I/O (io), 17 I/O (io), 18 I/O (io), 19 I/O (io), 20 I/O (io), 21 I/O (io), 22 VCC (power), 23 I/O (io), 24 I/O (io), 25 I/O (io), 26 I/O (io), 27 I/O (io), 28 I/O (io), 29 I/O (io), 30 I/O (io), 31 M1-~{RDATA} (out), 32 M0-RTRIG (in), 33 M2-I/O (io), 34 HDC-I/O (io), 35 I/O (io), 36 ~{LDC}-I/O (io), 37 I/O (io), 38 NC, 39 I/O (io), 40 I/O (io), 41 NC, 42 ~{INIT}-I/O (io), 43 GND (power), 44 I/O (io), 45 I/O (io), 46 I/O (io), 47 I/O (io), 48 I/O (io), 49 I/O (io), 50 NC, 51 NC, 52 I/O (io), 53 XTL2 (IN)-I/O (io), 54 ~{RESET} (in), 55 DONE-~{PROG} (out), 56 D7-I/O (io), 57 XTL1(OUT)-BCLKIN-I/O (io), 58 D6-I/O (io), 59 I/O (io), 60 D5-I/O (io), 61 ~{CS}0-I/O (io), 62 D4-I/O (io), 63 I/O (io), 64 VCC (power), 65 D3-I/O (io), 66 ~{CS}1-I/O (io), 67 D2-I/O (io), 68 I/O (io), 69 NC, 70 D1-I/O (io), 71 RDY/~{BUSY}-~{RCLK}-I/O (io), 72 DO-DIN-I/O (io), 73 DOUT-I/O (io), 74 CCLK (io), 75 A0-~{WS}-I/O (io), 76 A1-CS2-I/O (io), 77 A2-I/O (io), 78 A3-I/O (io), 79 NC, 80 NC, 81 A15-I/O (io), 82 A4-I/O (io), 83 A14-I/O (io), 84 A5-I/O (io)

## XC3020A-7PC84I
designator U?
Logic Cell Array with 64 CLBs, with 64 I/O Pins, 84-Pin PLCC, Industrial Grade; ComponentAvailability: Not for New Design
footprint PC84_N (Leaded Chip Carrier, 84-Leads, Body 29.3x29.3mm, Pitch 1.27mm, IPC Medium Density)
footprint PC84_L (Leaded Chip Carrier, 84-Leads, Body 29.3x29.3mm, Pitch 1.27mm, IPC High Density)
footprint PC84_M (Leaded Chip Carrier, 84-Leads, Body 29.3x29.3mm, Pitch 1.27mm, IPC Low Density)
3D model XC3020A-PC84 (84-Pin Plastic Leaded Chip Carrier (PC84))
pins: 1 GND (power), 2 A13-I/O (io), 3 A6-I/O (io), 4 A12-I/O (io), 5 A7-I/O (io), 6 NC, 7 NC, 8 A11-I/O (io), 9 A8-I/O (io), 10 A10-I/O (io), 11 A9-I/O (io), 12 ~{PWRDWN} (in), 13 TCLKIN-I/O (io), 14 NC, 15 I/O (io), 16 I/O (io), 17 I/O (io), 18 I/O (io), 19 I/O (io), 20 I/O (io), 21 I/O (io), 22 VCC (power), 23 I/O (io), 24 I/O (io), 25 I/O (io), 26 I/O (io), 27 I/O (io), 28 I/O (io), 29 I/O (io), 30 I/O (io), 31 M1-~{RDATA} (out), 32 M0-RTRIG (in), 33 M2-I/O (io), 34 HDC-I/O (io), 35 I/O (io), 36 ~{LDC}-I/O (io), 37 I/O (io), 38 NC, 39 I/O (io), 40 I/O (io), 41 NC, 42 ~{INIT}-I/O (io), 43 GND (power), 44 I/O (io), 45 I/O (io), 46 I/O (io), 47 I/O (io), 48 I/O (io), 49 I/O (io), 50 NC, 51 NC, 52 I/O (io), 53 XTL2 (IN)-I/O (io), 54 ~{RESET} (in), 55 DONE-~{PROG} (out), 56 D7-I/O (io), 57 XTL1(OUT)-BCLKIN-I/O (io), 58 D6-I/O (io), 59 I/O (io), 60 D5-I/O (io), 61 ~{CS}0-I/O (io), 62 D4-I/O (io), 63 I/O (io), 64 VCC (power), 65 D3-I/O (io), 66 ~{CS}1-I/O (io), 67 D2-I/O (io), 68 I/O (io), 69 NC, 70 D1-I/O (io), 71 RDY/~{BUSY}-~{RCLK}-I/O (io), 72 DO-DIN-I/O (io), 73 DOUT-I/O (io), 74 CCLK (io), 75 A0-~{WS}-I/O (io), 76 A1-CS2-I/O (io), 77 A2-I/O (io), 78 A3-I/O (io), 79 NC, 80 NC, 81 A15-I/O (io), 82 A4-I/O (io), 83 A14-I/O (io), 84 A5-I/O (io)

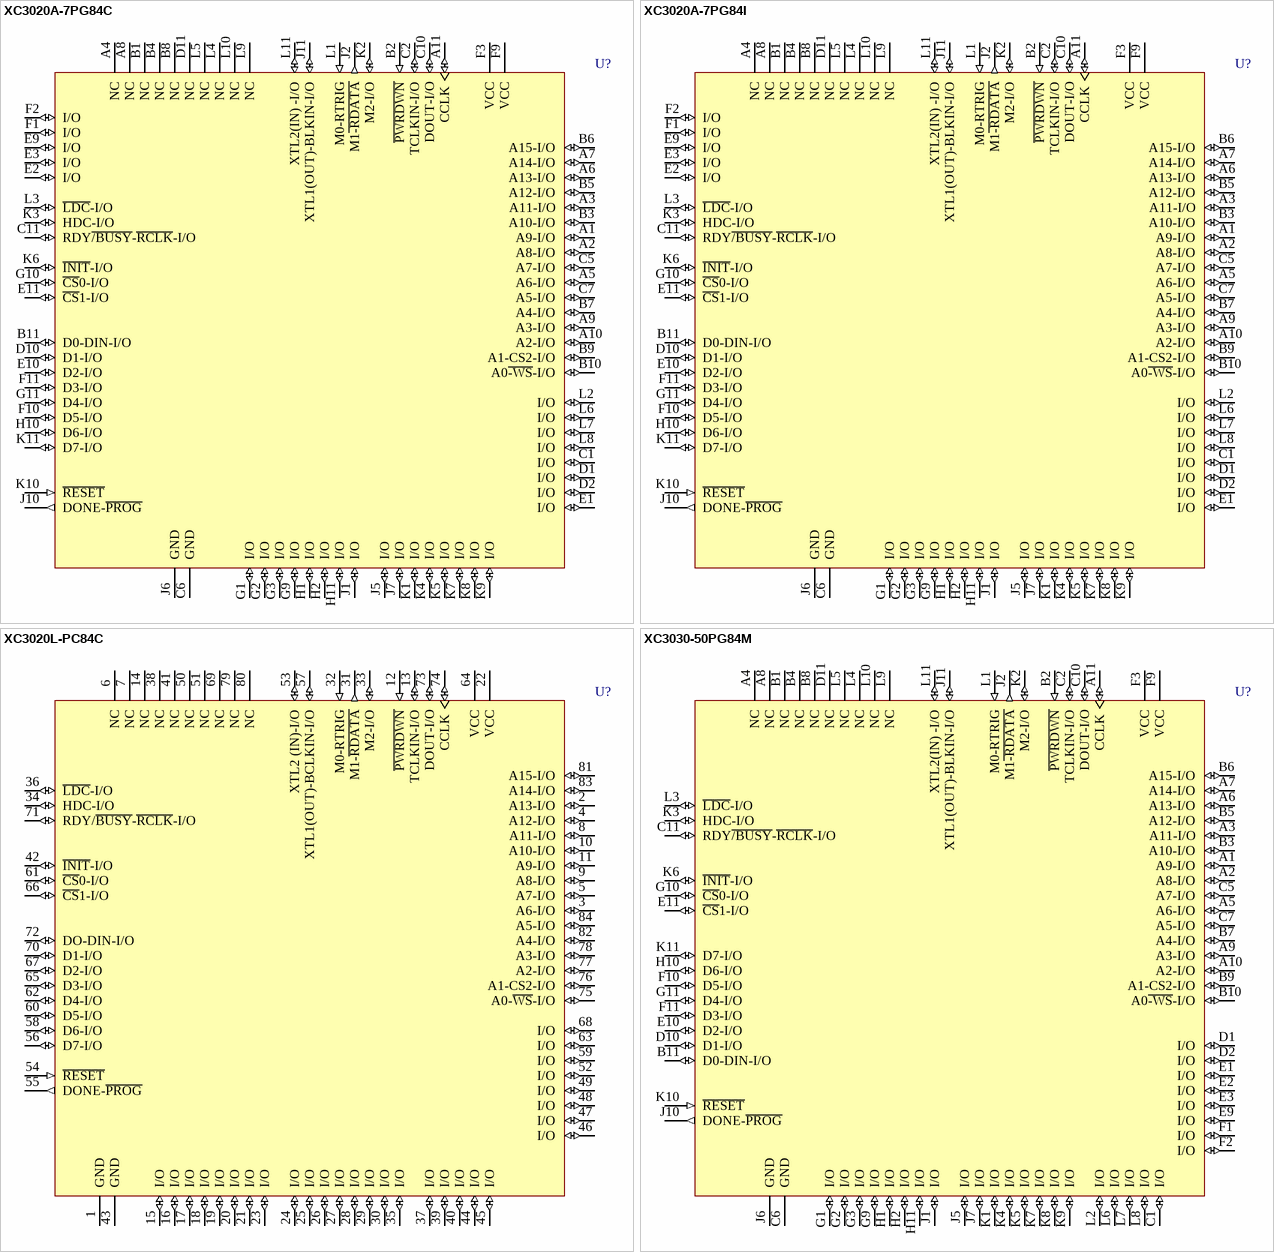
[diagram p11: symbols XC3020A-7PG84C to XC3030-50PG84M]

## XC3020A-7PG84C
designator U?
Logic Cell Array with 64 CLBs, with 64 I/O Pins, 84-Pin PGA, Commercial Grade; ComponentAvailability: Not for New Design
footprint PG84 (PGA, 85-Leads, Body 28x28mm, Pitch 2.54mm)
3D model XC3020A-PG84 (84-Pin Ceramic Pin Grid Array (PG84))
pins: A1 A9-I/O (io), A2 A8-I/O (io), A3 A11-I/O (io), A4 NC, A5 A6-I/O (io), A6 A13-I/O (io), A7 A14-I/O (io), A8 NC, A9 A3-I/O (io), A10 A2-I/O (io), A11 CCLK (io), B1 NC, B2 ~{PWRDWN} (in), B3 A10-I/O (io), B4 NC, B5 A12-I/O (io), B6 A15-I/O (io), B7 A4-I/O (io), B8 NC, B9 A1-CS2-I/O (io), B10 A0~{-WS}-I/O (io), B11 D0-DIN-I/O (io), C1 I/O (io), C2 TCLKIN-I/O (io), C5 A7-I/O (io), C6 GND (power), C7 A5-I/O (io), C10 DOUT-I/O (io), C11 RDY~{/BUSY}-~{RCLK}-I/O (io), D1 I/O (io), D2 I/O (io), D10 D1-I/O (io), D11 NC, E1 I/O (io), E2 I/O (io), E3 I/O (io), E9 I/O (io), E10 D2-I/O (io), E11 ~{CS}1-I/O (io), F1 I/O (io), F2 I/O (io), F3 VCC (power), F9 VCC (power), F10 D5-I/O (io), F11 D3-I/O (io), G1 I/O (io), G2 I/O (io), G3 I/O (io), G9 I/O (io), G10 ~{CS}0-I/O (io), G11 D4-I/O (io), H1 I/O (io), H2 I/O (io), H10 D6-I/O (io), H11 I/O (io), J1 I/O (io), J2 M1~{-RDATA} (out), J5 I/O (io), J6 GND (power), J7 I/O (io), J10 DONE-~{PROG} (out), J11 XTL1(OUT)-BLKIN-I/O (io), K1 I/O (io), K2 M2-I/O (io), K3 HDC-I/O (io), K4 I/O (io), K5 I/O (io), K6 ~{INIT}-I/O (io), K7 I/O (io), K8 I/O (io), K9 I/O (io), K10 ~{RESET} (in), K11 D7-I/O (io), L1 M0-RTRIG (in), L2 I/O (io), L3 ~{LDC}-I/O (io), L4 NC, L5 NC, L6 I/O (io), L7 I/O (io), L8 I/O (io), L9 NC, L10 NC, L11 XTL2(IN) -I/O (io)

## XC3020A-7PG84I
designator U?
Logic Cell Array with 64 CLBs, with 64 I/O Pins, 84-Pin PGA, Industrial Grade; ComponentAvailability: Not for New Design
footprint PG84 (PGA, 85-Leads, Body 28x28mm, Pitch 2.54mm)
3D model XC3020A-PG84 (84-Pin Ceramic Pin Grid Array (PG84))
pins: A1 A9-I/O (io), A2 A8-I/O (io), A3 A11-I/O (io), A4 NC, A5 A6-I/O (io), A6 A13-I/O (io), A7 A14-I/O (io), A8 NC, A9 A3-I/O (io), A10 A2-I/O (io), A11 CCLK (io), B1 NC, B2 ~{PWRDWN} (in), B3 A10-I/O (io), B4 NC, B5 A12-I/O (io), B6 A15-I/O (io), B7 A4-I/O (io), B8 NC, B9 A1-CS2-I/O (io), B10 A0~{-WS}-I/O (io), B11 D0-DIN-I/O (io), C1 I/O (io), C2 TCLKIN-I/O (io), C5 A7-I/O (io), C6 GND (power), C7 A5-I/O (io), C10 DOUT-I/O (io), C11 RDY~{/BUSY}-~{RCLK}-I/O (io), D1 I/O (io), D2 I/O (io), D10 D1-I/O (io), D11 NC, E1 I/O (io), E2 I/O (io), E3 I/O (io), E9 I/O (io), E10 D2-I/O (io), E11 ~{CS}1-I/O (io), F1 I/O (io), F2 I/O (io), F3 VCC (power), F9 VCC (power), F10 D5-I/O (io), F11 D3-I/O (io), G1 I/O (io), G2 I/O (io), G3 I/O (io), G9 I/O (io), G10 ~{CS}0-I/O (io), G11 D4-I/O (io), H1 I/O (io), H2 I/O (io), H10 D6-I/O (io), H11 I/O (io), J1 I/O (io), J2 M1~{-RDATA} (out), J5 I/O (io), J6 GND (power), J7 I/O (io), J10 DONE-~{PROG} (out), J11 XTL1(OUT)-BLKIN-I/O (io), K1 I/O (io), K2 M2-I/O (io), K3 HDC-I/O (io), K4 I/O (io), K5 I/O (io), K6 ~{INIT}-I/O (io), K7 I/O (io), K8 I/O (io), K9 I/O (io), K10 ~{RESET} (in), K11 D7-I/O (io), L1 M0-RTRIG (in), L2 I/O (io), L3 ~{LDC}-I/O (io), L4 NC, L5 NC, L6 I/O (io), L7 I/O (io), L8 I/O (io), L9 NC, L10 NC, L11 XTL2(IN) -I/O (io)

## XC3020L-PC84C
designator U?
Logic Cell Array with 64 CLBs, with 64 I/O Pins, 84-Pin PLCC, Commercial Grade; ComponentAvailability: Not for New Design
footprint PC84_N (Leaded Chip Carrier, 84-Leads, Body 29.3x29.3mm, Pitch 1.27mm, IPC Medium Density)
footprint PC84_L (Leaded Chip Carrier, 84-Leads, Body 29.3x29.3mm, Pitch 1.27mm, IPC High Density)
footprint PC84_M (Leaded Chip Carrier, 84-Leads, Body 29.3x29.3mm, Pitch 1.27mm, IPC Low Density)
3D model XC3020L-PC84 (84-Pin Plastic Leaded Chip Carrier (PC84))
pins: 1 GND (power), 2 A13-I/O (io), 3 A6-I/O (io), 4 A12-I/O (io), 5 A7-I/O (io), 6 NC, 7 NC, 8 A11-I/O (io), 9 A8-I/O (io), 10 A10-I/O (io), 11 A9-I/O (io), 12 ~{PWRDWN} (in), 13 TCLKIN-I/O (io), 14 NC, 15 I/O (io), 16 I/O (io), 17 I/O (io), 18 I/O (io), 19 I/O (io), 20 I/O (io), 21 I/O (io), 22 VCC (power), 23 I/O (io), 24 I/O (io), 25 I/O (io), 26 I/O (io), 27 I/O (io), 28 I/O (io), 29 I/O (io), 30 I/O (io), 31 M1-~{RDATA} (out), 32 M0-RTRIG (in), 33 M2-I/O (io), 34 HDC-I/O (io), 35 I/O (io), 36 ~{LDC}-I/O (io), 37 I/O (io), 38 NC, 39 I/O (io), 40 I/O (io), 41 NC, 42 ~{INIT}-I/O (io), 43 GND (power), 44 I/O (io), 45 I/O (io), 46 I/O (io), 47 I/O (io), 48 I/O (io), 49 I/O (io), 50 NC, 51 NC, 52 I/O (io), 53 XTL2 (IN)-I/O (io), 54 ~{RESET} (in), 55 DONE-~{PROG} (out), 56 D7-I/O (io), 57 XTL1(OUT)-BCLKIN-I/O (io), 58 D6-I/O (io), 59 I/O (io), 60 D5-I/O (io), 61 ~{CS}0-I/O (io), 62 D4-I/O (io), 63 I/O (io), 64 VCC (power), 65 D3-I/O (io), 66 ~{CS}1-I/O (io), 67 D2-I/O (io), 68 I/O (io), 69 NC, 70 D1-I/O (io), 71 RDY/~{BUSY}-~{RCLK}-I/O (io), 72 DO-DIN-I/O (io), 73 DOUT-I/O (io), 74 CCLK (io), 75 A0-~{WS}-I/O (io), 76 A1-CS2-I/O (io), 77 A2-I/O (io), 78 A3-I/O (io), 79 NC, 80 NC, 81 A15-I/O (io), 82 A4-I/O (io), 83 A14-I/O (io), 84 A5-I/O (io)

## XC3030-50PG84M
designator U?
Logic Cell Array with 100 CLBs, with 64 I/O Pins, 84-Pin PGA, Military Grade; ComponentAvailability: Not for New Design
footprint PG84 (PGA, 85-Leads, Body 28x28mm, Pitch 2.54mm)
3D model XC3030-PG84 (84-Pin Ceramic Pin Grid Array (PG84))
pins: A1 A9-I/O (io), A2 A8-I/O (io), A3 A11-I/O (io), A4 NC, A5 A6-I/O (io), A6 A13-I/O (io), A7 A14-I/O (io), A8 NC, A9 A3-I/O (io), A10 A2-I/O (io), A11 CCLK (io), B1 NC, B2 ~{PWRDWN} (in), B3 A10-I/O (io), B4 NC, B5 A12-I/O (io), B6 A15-I/O (io), B7 A4-I/O (io), B8 NC, B9 A1-CS2-I/O (io), B10 A0~{-WS}-I/O (io), B11 D0-DIN-I/O (io), C1 I/O (io), C2 TCLKIN-I/O (io), C5 A7-I/O (io), C6 GND (power), C7 A5-I/O (io), C10 DOUT-I/O (io), C11 RDY~{/BUSY}-~{RCLK}-I/O (io), D1 I/O (io), D2 I/O (io), D10 D1-I/O (io), D11 NC, E1 I/O (io), E2 I/O (io), E3 I/O (io), E9 I/O (io), E10 D2-I/O (io), E11 ~{CS}1-I/O (io), F1 I/O (io), F2 I/O (io), F3 VCC (power), F9 VCC (power), F10 D5-I/O (io), F11 D3-I/O (io), G1 I/O (io), G2 I/O (io), G3 I/O (io), G9 I/O (io), G10 ~{CS}0-I/O (io), G11 D4-I/O (io), H1 I/O (io), H2 I/O (io), H10 D6-I/O (io), H11 I/O (io), J1 I/O (io), J2 M1~{-RDATA} (out), J5 I/O (io), J6 GND (power), J7 I/O (io), J10 DONE-~{PROG} (out), J11 XTL1(OUT)-BLKIN-I/O (io), K1 I/O (io), K2 M2-I/O (io), K3 HDC-I/O (io), K4 I/O (io), K5 I/O (io), K6 ~{INIT}-I/O (io), K7 I/O (io), K8 I/O (io), K9 I/O (io), K10 ~{RESET} (in), K11 D7-I/O (io), L1 M0-RTRIG (in), L2 I/O (io), L3 ~{LDC}-I/O (io), L4 NC, L5 NC, L6 I/O (io), L7 I/O (io), L8 I/O (io), L9 NC, L10 NC, L11 XTL2(IN) -I/O (io)

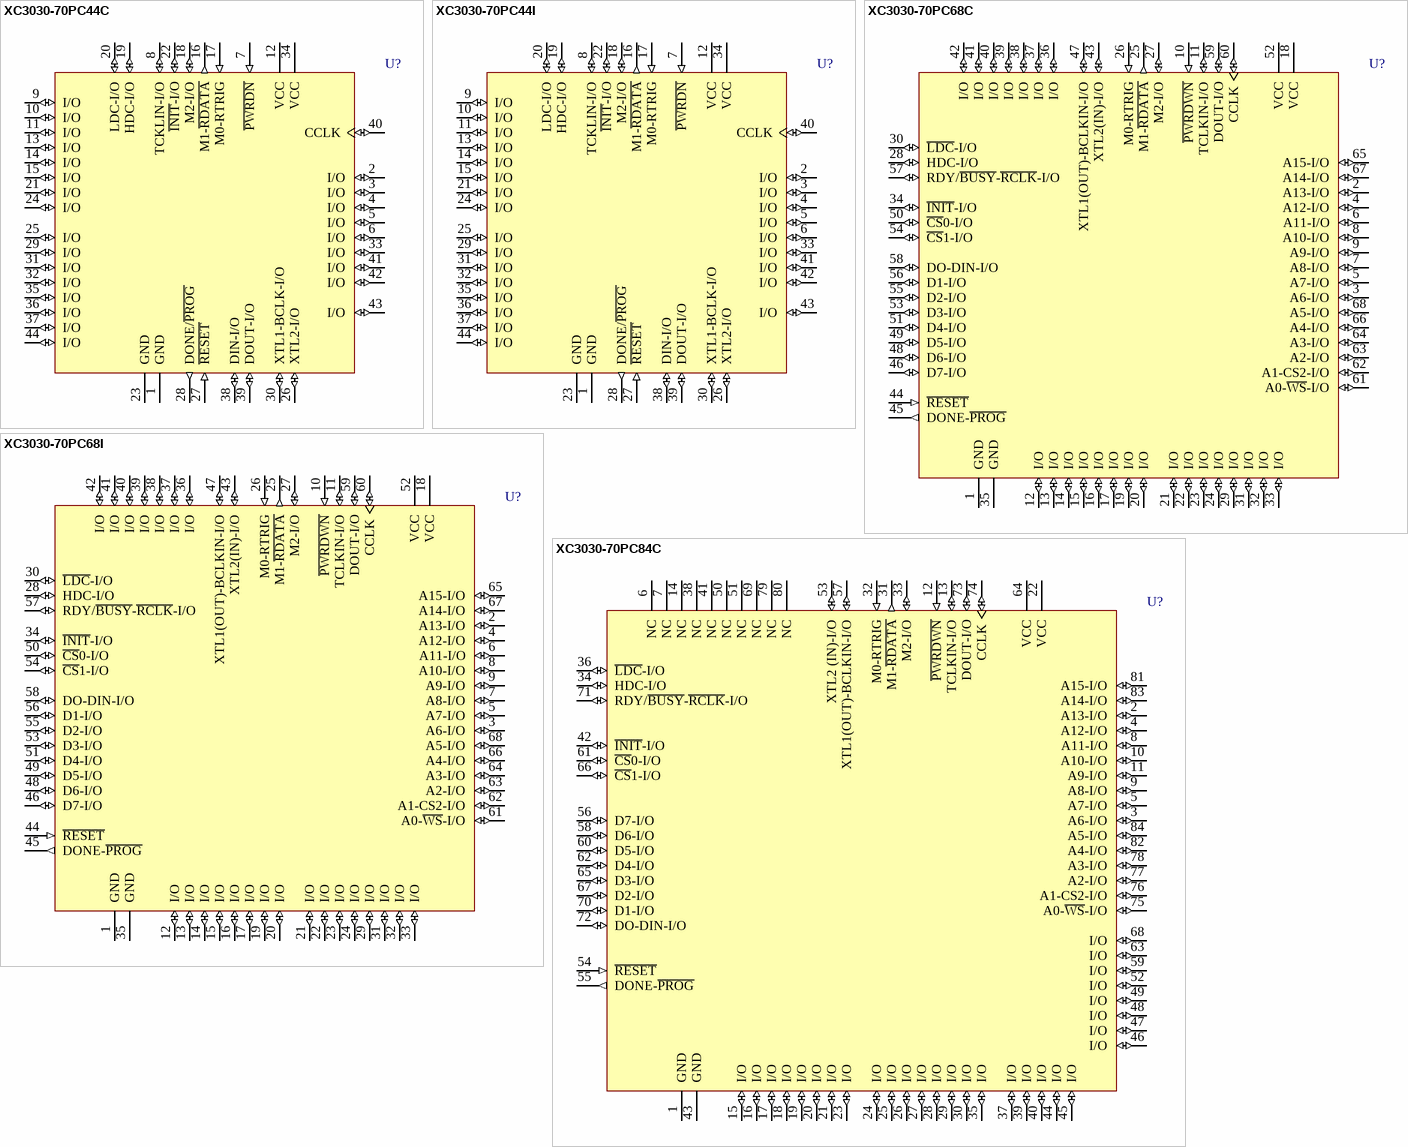
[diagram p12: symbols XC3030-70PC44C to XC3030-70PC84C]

## XC3030-70PC44C
designator U?
Logic Cell Array with 100 CLBs, with 34 I/O Pins, 44-Pin PLCC, Commercial Grade; ComponentAvailability: Not for New Design
footprint PC44_N (Leaded Chip Carrier, 44-Leads, Body 16.6x16.6mm, Pitch 1.27mm, IPC Medium Density)
footprint PC44_L (Leaded Chip Carrier, 44-Leads, Body 16.6x16.6mm, Pitch 1.27mm, IPC High Density)
footprint PC44_M (Leaded Chip Carrier, 44-Leads, Body 16.6x16.6mm, Pitch 1.27mm, IPC Low Density)
3D model XC3030-PC44 (44-Pin Plastic Leaded Chip Carrier (PC44))
pins: 1 GND (power), 2 I/O (io), 3 I/O (io), 4 I/O (io), 5 I/O (io), 6 I/O (io), 7 ~{PWRDN} (in), 8 TCKLIN-I/O (io), 9 I/O (io), 10 I/O (io), 11 I/O (io), 12 VCC (power), 13 I/O (io), 14 I/O (io), 15 I/O (io), 16 M1-~{RDATA} (out), 17 M0-RTRIG (in), 18 M2-I/O (io), 19 HDC-I/O (io), 20 LDC-I/O (io), 21 I/O (io), 22 ~{INIT}-I/O (io), 23 GND (power), 24 I/O (io), 25 I/O (io), 26 XTL2-I/O (io), 27 ~{RESET} (in), 28 DONE/~{PROG} (out), 29 I/O (io), 30 XTL1-BCLK-I/O (io), 31 I/O (io), 32 I/O (io), 33 I/O (io), 34 VCC (power), 35 I/O (io), 36 I/O (io), 37 I/O (io), 38 DIN-I/O (io), 39 DOUT-I/O (io), 40 CCLK (io), 41 I/O (io), 42 I/O (io), 43 I/O (io), 44 I/O (io)

## XC3030-70PC44I
designator U?
Logic Cell Array with 100 CLBs, with 34 I/O Pins, 44-Pin PLCC, Industrial Grade; ComponentAvailability: Not for New Design
footprint PC44_N (Leaded Chip Carrier, 44-Leads, Body 16.6x16.6mm, Pitch 1.27mm, IPC Medium Density)
footprint PC44_L (Leaded Chip Carrier, 44-Leads, Body 16.6x16.6mm, Pitch 1.27mm, IPC High Density)
footprint PC44_M (Leaded Chip Carrier, 44-Leads, Body 16.6x16.6mm, Pitch 1.27mm, IPC Low Density)
3D model XC3030-PC44 (44-Pin Plastic Leaded Chip Carrier (PC44))
pins: 1 GND (power), 2 I/O (io), 3 I/O (io), 4 I/O (io), 5 I/O (io), 6 I/O (io), 7 ~{PWRDN} (in), 8 TCKLIN-I/O (io), 9 I/O (io), 10 I/O (io), 11 I/O (io), 12 VCC (power), 13 I/O (io), 14 I/O (io), 15 I/O (io), 16 M1-~{RDATA} (out), 17 M0-RTRIG (in), 18 M2-I/O (io), 19 HDC-I/O (io), 20 LDC-I/O (io), 21 I/O (io), 22 ~{INIT}-I/O (io), 23 GND (power), 24 I/O (io), 25 I/O (io), 26 XTL2-I/O (io), 27 ~{RESET} (in), 28 DONE/~{PROG} (out), 29 I/O (io), 30 XTL1-BCLK-I/O (io), 31 I/O (io), 32 I/O (io), 33 I/O (io), 34 VCC (power), 35 I/O (io), 36 I/O (io), 37 I/O (io), 38 DIN-I/O (io), 39 DOUT-I/O (io), 40 CCLK (io), 41 I/O (io), 42 I/O (io), 43 I/O (io), 44 I/O (io)

## XC3030-70PC68C
designator U?
Logic Cell Array with 100 CLBs, with 58 I/O Pins, 68-Pin PLCC, Commercial Grade; ComponentAvailability: Not for New Design
footprint PC68_N (Leaded Chip Carrier, 68-Leads, Body 24x24mm, Pitch 1.27mm, IPC Medium Density)
footprint PC68_L (Leaded Chip Carrier, 68-Leads, Body 24x24mm, Pitch 1.27mm, IPC High Density)
footprint PC68_M (Leaded Chip Carrier, 68-Leads, Body 24x24mm, Pitch 1.27mm, IPC Low Density)
3D model XC3030-PC68 (68-Pin Plastic Leaded Chip Carrier (PC68))
pins: 1 GND (power), 2 A13-I/O (io), 3 A6-I/O (io), 4 A12-I/O (io), 5 A7-I/O (io), 6 A11-I/O (io), 7 A8-I/O (io), 8 A10-I/O (io), 9 A9-I/O (io), 10 ~{PWRDWN} (in), 11 TCLKIN-I/O (io), 12 I/O (io), 13 I/O (io), 14 I/O (io), 15 I/O (io), 16 I/O (io), 17 I/O (io), 18 VCC (power), 19 I/O (io), 20 I/O (io), 21 I/O (io), 22 I/O (io), 23 I/O (io), 24 I/O (io), 25 M1-~{RDATA} (out), 26 M0-RTRIG (in), 27 M2-I/O (io), 28 HDC-I/O (io), 29 I/O (io), 30 ~{LDC}-I/O (io), 31 I/O (io), 32 I/O (io), 33 I/O (io), 34 ~{INIT}-I/O (io), 35 GND (power), 36 I/O (io), 37 I/O (io), 38 I/O (io), 39 I/O (io), 40 I/O (io), 41 I/O (io), 42 I/O (io), 43 XTL2(IN)-I/O (io), 44 ~{RESET} (in), 45 DONE-~{PROG} (out), 46 D7-I/O (io), 47 XTL1(OUT)-BCLKIN-I/O (io), 48 D6-I/O (io), 49 D5-I/O (io), 50 ~{CS}0-I/O (io), 51 D4-I/O (io), 52 VCC (power), 53 D3-I/O (io), 54 ~{CS}1-I/O (io), 55 D2-I/O (io), 56 D1-I/O (io), 57 RDY/~{BUSY}-~{RCLK}-I/O (io), 58 DO-DIN-I/O (io), 59 DOUT-I/O (io), 60 CCLK (io), 61 A0-~{WS}-I/O (io), 62 A1-CS2-I/O (io), 63 A2-I/O (io), 64 A3-I/O (io), 65 A15-I/O (io), 66 A4-I/O (io), 67 A14-I/O (io), 68 A5-I/O (io)

## XC3030-70PC68I
designator U?
Logic Cell Array with 100 CLBs, with 58 I/O Pins, 68-Pin PLCC, Industrial Grade; ComponentAvailability: Not for New Design
footprint PC68_N (Leaded Chip Carrier, 68-Leads, Body 24x24mm, Pitch 1.27mm, IPC Medium Density)
footprint PC68_L (Leaded Chip Carrier, 68-Leads, Body 24x24mm, Pitch 1.27mm, IPC High Density)
footprint PC68_M (Leaded Chip Carrier, 68-Leads, Body 24x24mm, Pitch 1.27mm, IPC Low Density)
3D model XC3030-PC68 (68-Pin Plastic Leaded Chip Carrier (PC68))
pins: 1 GND (power), 2 A13-I/O (io), 3 A6-I/O (io), 4 A12-I/O (io), 5 A7-I/O (io), 6 A11-I/O (io), 7 A8-I/O (io), 8 A10-I/O (io), 9 A9-I/O (io), 10 ~{PWRDWN} (in), 11 TCLKIN-I/O (io), 12 I/O (io), 13 I/O (io), 14 I/O (io), 15 I/O (io), 16 I/O (io), 17 I/O (io), 18 VCC (power), 19 I/O (io), 20 I/O (io), 21 I/O (io), 22 I/O (io), 23 I/O (io), 24 I/O (io), 25 M1-~{RDATA} (out), 26 M0-RTRIG (in), 27 M2-I/O (io), 28 HDC-I/O (io), 29 I/O (io), 30 ~{LDC}-I/O (io), 31 I/O (io), 32 I/O (io), 33 I/O (io), 34 ~{INIT}-I/O (io), 35 GND (power), 36 I/O (io), 37 I/O (io), 38 I/O (io), 39 I/O (io), 40 I/O (io), 41 I/O (io), 42 I/O (io), 43 XTL2(IN)-I/O (io), 44 ~{RESET} (in), 45 DONE-~{PROG} (out), 46 D7-I/O (io), 47 XTL1(OUT)-BCLKIN-I/O (io), 48 D6-I/O (io), 49 D5-I/O (io), 50 ~{CS}0-I/O (io), 51 D4-I/O (io), 52 VCC (power), 53 D3-I/O (io), 54 ~{CS}1-I/O (io), 55 D2-I/O (io), 56 D1-I/O (io), 57 RDY/~{BUSY}-~{RCLK}-I/O (io), 58 DO-DIN-I/O (io), 59 DOUT-I/O (io), 60 CCLK (io), 61 A0-~{WS}-I/O (io), 62 A1-CS2-I/O (io), 63 A2-I/O (io), 64 A3-I/O (io), 65 A15-I/O (io), 66 A4-I/O (io), 67 A14-I/O (io), 68 A5-I/O (io)

## XC3030-70PC84C
designator U?
Logic Cell Array with 100 CLBs, with 64 I/O Pins, 84-Pin PLCC, Commercial Grade; ComponentAvailability: Not for New Design
footprint PC84_N (Leaded Chip Carrier, 84-Leads, Body 29.3x29.3mm, Pitch 1.27mm, IPC Medium Density)
footprint PC84_L (Leaded Chip Carrier, 84-Leads, Body 29.3x29.3mm, Pitch 1.27mm, IPC High Density)
footprint PC84_M (Leaded Chip Carrier, 84-Leads, Body 29.3x29.3mm, Pitch 1.27mm, IPC Low Density)
3D model XC3030-PC84 (84-Pin Plastic Leaded Chip Carrier (PC84))
pins: 1 GND (power), 2 A13-I/O (io), 3 A6-I/O (io), 4 A12-I/O (io), 5 A7-I/O (io), 6 NC, 7 NC, 8 A11-I/O (io), 9 A8-I/O (io), 10 A10-I/O (io), 11 A9-I/O (io), 12 ~{PWRDWN} (in), 13 TCLKIN-I/O (io), 14 NC, 15 I/O (io), 16 I/O (io), 17 I/O (io), 18 I/O (io), 19 I/O (io), 20 I/O (io), 21 I/O (io), 22 VCC (power), 23 I/O (io), 24 I/O (io), 25 I/O (io), 26 I/O (io), 27 I/O (io), 28 I/O (io), 29 I/O (io), 30 I/O (io), 31 M1-~{RDATA} (out), 32 M0-RTRIG (in), 33 M2-I/O (io), 34 HDC-I/O (io), 35 I/O (io), 36 ~{LDC}-I/O (io), 37 I/O (io), 38 NC, 39 I/O (io), 40 I/O (io), 41 NC, 42 ~{INIT}-I/O (io), 43 GND (power), 44 I/O (io), 45 I/O (io), 46 I/O (io), 47 I/O (io), 48 I/O (io), 49 I/O (io), 50 NC, 51 NC, 52 I/O (io), 53 XTL2 (IN)-I/O (io), 54 ~{RESET} (in), 55 DONE-~{PROG} (out), 56 D7-I/O (io), 57 XTL1(OUT)-BCLKIN-I/O (io), 58 D6-I/O (io), 59 I/O (io), 60 D5-I/O (io), 61 ~{CS}0-I/O (io), 62 D4-I/O (io), 63 I/O (io), 64 VCC (power), 65 D3-I/O (io), 66 ~{CS}1-I/O (io), 67 D2-I/O (io), 68 I/O (io), 69 NC, 70 D1-I/O (io), 71 RDY/~{BUSY}-~{RCLK}-I/O (io), 72 DO-DIN-I/O (io), 73 DOUT-I/O (io), 74 CCLK (io), 75 A0-~{WS}-I/O (io), 76 A1-CS2-I/O (io), 77 A2-I/O (io), 78 A3-I/O (io), 79 NC, 80 NC, 81 A15-I/O (io), 82 A4-I/O (io), 83 A14-I/O (io), 84 A5-I/O (io)

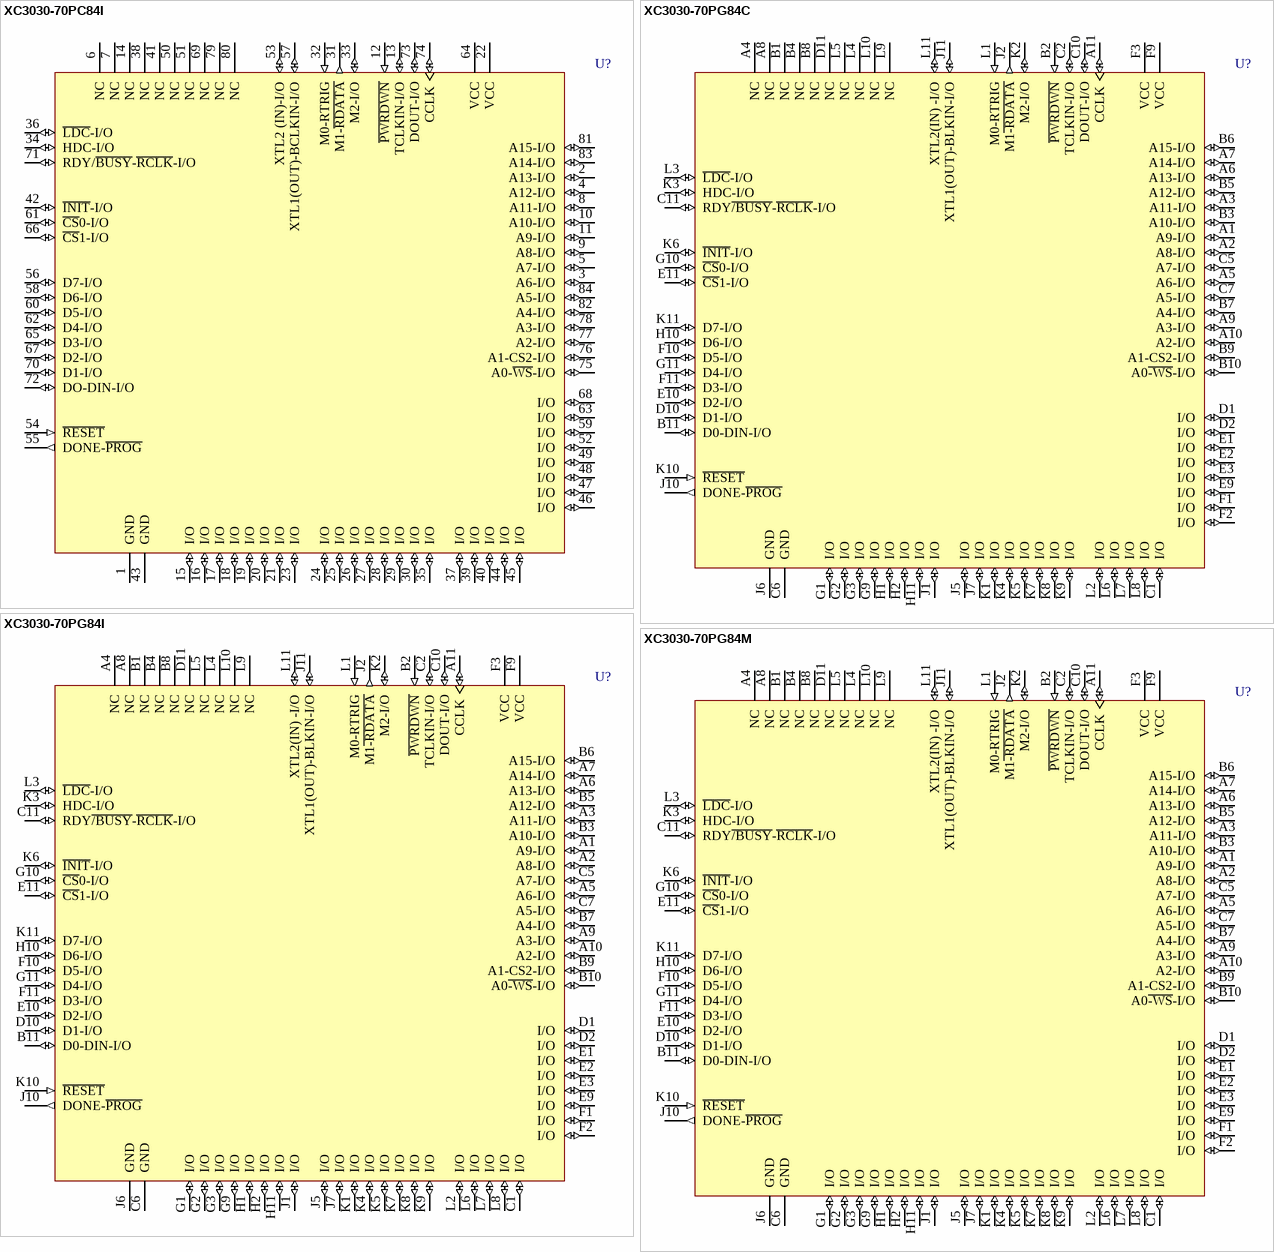
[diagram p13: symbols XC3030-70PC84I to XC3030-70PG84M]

## XC3030-70PC84I
designator U?
Logic Cell Array with 100 CLBs, with 64 I/O Pins, 84-Pin PLCC, Industrial Grade; ComponentAvailability: Not for New Design
footprint PC84_N (Leaded Chip Carrier, 84-Leads, Body 29.3x29.3mm, Pitch 1.27mm, IPC Medium Density)
footprint PC84_L (Leaded Chip Carrier, 84-Leads, Body 29.3x29.3mm, Pitch 1.27mm, IPC High Density)
footprint PC84_M (Leaded Chip Carrier, 84-Leads, Body 29.3x29.3mm, Pitch 1.27mm, IPC Low Density)
3D model XC3030-PC84 (84-Pin Plastic Leaded Chip Carrier (PC84))
pins: 1 GND (power), 2 A13-I/O (io), 3 A6-I/O (io), 4 A12-I/O (io), 5 A7-I/O (io), 6 NC, 7 NC, 8 A11-I/O (io), 9 A8-I/O (io), 10 A10-I/O (io), 11 A9-I/O (io), 12 ~{PWRDWN} (in), 13 TCLKIN-I/O (io), 14 NC, 15 I/O (io), 16 I/O (io), 17 I/O (io), 18 I/O (io), 19 I/O (io), 20 I/O (io), 21 I/O (io), 22 VCC (power), 23 I/O (io), 24 I/O (io), 25 I/O (io), 26 I/O (io), 27 I/O (io), 28 I/O (io), 29 I/O (io), 30 I/O (io), 31 M1-~{RDATA} (out), 32 M0-RTRIG (in), 33 M2-I/O (io), 34 HDC-I/O (io), 35 I/O (io), 36 ~{LDC}-I/O (io), 37 I/O (io), 38 NC, 39 I/O (io), 40 I/O (io), 41 NC, 42 ~{INIT}-I/O (io), 43 GND (power), 44 I/O (io), 45 I/O (io), 46 I/O (io), 47 I/O (io), 48 I/O (io), 49 I/O (io), 50 NC, 51 NC, 52 I/O (io), 53 XTL2 (IN)-I/O (io), 54 ~{RESET} (in), 55 DONE-~{PROG} (out), 56 D7-I/O (io), 57 XTL1(OUT)-BCLKIN-I/O (io), 58 D6-I/O (io), 59 I/O (io), 60 D5-I/O (io), 61 ~{CS}0-I/O (io), 62 D4-I/O (io), 63 I/O (io), 64 VCC (power), 65 D3-I/O (io), 66 ~{CS}1-I/O (io), 67 D2-I/O (io), 68 I/O (io), 69 NC, 70 D1-I/O (io), 71 RDY/~{BUSY}-~{RCLK}-I/O (io), 72 DO-DIN-I/O (io), 73 DOUT-I/O (io), 74 CCLK (io), 75 A0-~{WS}-I/O (io), 76 A1-CS2-I/O (io), 77 A2-I/O (io), 78 A3-I/O (io), 79 NC, 80 NC, 81 A15-I/O (io), 82 A4-I/O (io), 83 A14-I/O (io), 84 A5-I/O (io)

## XC3030-70PG84C
designator U?
Logic Cell Array with 100 CLBs, with 64 I/O Pins, 84-Pin PGA, Commercial Grade; ComponentAvailability: Not for New Design
footprint PG84 (PGA, 85-Leads, Body 28x28mm, Pitch 2.54mm)
3D model XC3030-PG84 (84-Pin Ceramic Pin Grid Array (PG84))
pins: A1 A9-I/O (io), A2 A8-I/O (io), A3 A11-I/O (io), A4 NC, A5 A6-I/O (io), A6 A13-I/O (io), A7 A14-I/O (io), A8 NC, A9 A3-I/O (io), A10 A2-I/O (io), A11 CCLK (io), B1 NC, B2 ~{PWRDWN} (in), B3 A10-I/O (io), B4 NC, B5 A12-I/O (io), B6 A15-I/O (io), B7 A4-I/O (io), B8 NC, B9 A1-CS2-I/O (io), B10 A0~{-WS}-I/O (io), B11 D0-DIN-I/O (io), C1 I/O (io), C2 TCLKIN-I/O (io), C5 A7-I/O (io), C6 GND (power), C7 A5-I/O (io), C10 DOUT-I/O (io), C11 RDY~{/BUSY}-~{RCLK}-I/O (io), D1 I/O (io), D2 I/O (io), D10 D1-I/O (io), D11 NC, E1 I/O (io), E2 I/O (io), E3 I/O (io), E9 I/O (io), E10 D2-I/O (io), E11 ~{CS}1-I/O (io), F1 I/O (io), F2 I/O (io), F3 VCC (power), F9 VCC (power), F10 D5-I/O (io), F11 D3-I/O (io), G1 I/O (io), G2 I/O (io), G3 I/O (io), G9 I/O (io), G10 ~{CS}0-I/O (io), G11 D4-I/O (io), H1 I/O (io), H2 I/O (io), H10 D6-I/O (io), H11 I/O (io), J1 I/O (io), J2 M1~{-RDATA} (out), J5 I/O (io), J6 GND (power), J7 I/O (io), J10 DONE-~{PROG} (out), J11 XTL1(OUT)-BLKIN-I/O (io), K1 I/O (io), K2 M2-I/O (io), K3 HDC-I/O (io), K4 I/O (io), K5 I/O (io), K6 ~{INIT}-I/O (io), K7 I/O (io), K8 I/O (io), K9 I/O (io), K10 ~{RESET} (in), K11 D7-I/O (io), L1 M0-RTRIG (in), L2 I/O (io), L3 ~{LDC}-I/O (io), L4 NC, L5 NC, L6 I/O (io), L7 I/O (io), L8 I/O (io), L9 NC, L10 NC, L11 XTL2(IN) -I/O (io)

## XC3030-70PG84I
designator U?
Logic Cell Array with 100 CLBs, with 64 I/O Pins, 84-Pin PGA, Industrial Grade; ComponentAvailability: Not for New Design
footprint PG84 (PGA, 85-Leads, Body 28x28mm, Pitch 2.54mm)
3D model XC3030-PG84 (84-Pin Ceramic Pin Grid Array (PG84))
pins: A1 A9-I/O (io), A2 A8-I/O (io), A3 A11-I/O (io), A4 NC, A5 A6-I/O (io), A6 A13-I/O (io), A7 A14-I/O (io), A8 NC, A9 A3-I/O (io), A10 A2-I/O (io), A11 CCLK (io), B1 NC, B2 ~{PWRDWN} (in), B3 A10-I/O (io), B4 NC, B5 A12-I/O (io), B6 A15-I/O (io), B7 A4-I/O (io), B8 NC, B9 A1-CS2-I/O (io), B10 A0~{-WS}-I/O (io), B11 D0-DIN-I/O (io), C1 I/O (io), C2 TCLKIN-I/O (io), C5 A7-I/O (io), C6 GND (power), C7 A5-I/O (io), C10 DOUT-I/O (io), C11 RDY~{/BUSY}-~{RCLK}-I/O (io), D1 I/O (io), D2 I/O (io), D10 D1-I/O (io), D11 NC, E1 I/O (io), E2 I/O (io), E3 I/O (io), E9 I/O (io), E10 D2-I/O (io), E11 ~{CS}1-I/O (io), F1 I/O (io), F2 I/O (io), F3 VCC (power), F9 VCC (power), F10 D5-I/O (io), F11 D3-I/O (io), G1 I/O (io), G2 I/O (io), G3 I/O (io), G9 I/O (io), G10 ~{CS}0-I/O (io), G11 D4-I/O (io), H1 I/O (io), H2 I/O (io), H10 D6-I/O (io), H11 I/O (io), J1 I/O (io), J2 M1~{-RDATA} (out), J5 I/O (io), J6 GND (power), J7 I/O (io), J10 DONE-~{PROG} (out), J11 XTL1(OUT)-BLKIN-I/O (io), K1 I/O (io), K2 M2-I/O (io), K3 HDC-I/O (io), K4 I/O (io), K5 I/O (io), K6 ~{INIT}-I/O (io), K7 I/O (io), K8 I/O (io), K9 I/O (io), K10 ~{RESET} (in), K11 D7-I/O (io), L1 M0-RTRIG (in), L2 I/O (io), L3 ~{LDC}-I/O (io), L4 NC, L5 NC, L6 I/O (io), L7 I/O (io), L8 I/O (io), L9 NC, L10 NC, L11 XTL2(IN) -I/O (io)

## XC3030-70PG84M
designator U?
Logic Cell Array with 100 CLBs, with 64 I/O Pins, 84-Pin PGA, Military Grade; ComponentAvailability: Not for New Design
footprint PG84 (PGA, 85-Leads, Body 28x28mm, Pitch 2.54mm)
3D model XC3030-PG84 (84-Pin Ceramic Pin Grid Array (PG84))
pins: A1 A9-I/O (io), A2 A8-I/O (io), A3 A11-I/O (io), A4 NC, A5 A6-I/O (io), A6 A13-I/O (io), A7 A14-I/O (io), A8 NC, A9 A3-I/O (io), A10 A2-I/O (io), A11 CCLK (io), B1 NC, B2 ~{PWRDWN} (in), B3 A10-I/O (io), B4 NC, B5 A12-I/O (io), B6 A15-I/O (io), B7 A4-I/O (io), B8 NC, B9 A1-CS2-I/O (io), B10 A0~{-WS}-I/O (io), B11 D0-DIN-I/O (io), C1 I/O (io), C2 TCLKIN-I/O (io), C5 A7-I/O (io), C6 GND (power), C7 A5-I/O (io), C10 DOUT-I/O (io), C11 RDY~{/BUSY}-~{RCLK}-I/O (io), D1 I/O (io), D2 I/O (io), D10 D1-I/O (io), D11 NC, E1 I/O (io), E2 I/O (io), E3 I/O (io), E9 I/O (io), E10 D2-I/O (io), E11 ~{CS}1-I/O (io), F1 I/O (io), F2 I/O (io), F3 VCC (power), F9 VCC (power), F10 D5-I/O (io), F11 D3-I/O (io), G1 I/O (io), G2 I/O (io), G3 I/O (io), G9 I/O (io), G10 ~{CS}0-I/O (io), G11 D4-I/O (io), H1 I/O (io), H2 I/O (io), H10 D6-I/O (io), H11 I/O (io), J1 I/O (io), J2 M1~{-RDATA} (out), J5 I/O (io), J6 GND (power), J7 I/O (io), J10 DONE-~{PROG} (out), J11 XTL1(OUT)-BLKIN-I/O (io), K1 I/O (io), K2 M2-I/O (io), K3 HDC-I/O (io), K4 I/O (io), K5 I/O (io), K6 ~{INIT}-I/O (io), K7 I/O (io), K8 I/O (io), K9 I/O (io), K10 ~{RESET} (in), K11 D7-I/O (io), L1 M0-RTRIG (in), L2 I/O (io), L3 ~{LDC}-I/O (io), L4 NC, L5 NC, L6 I/O (io), L7 I/O (io), L8 I/O (io), L9 NC, L10 NC, L11 XTL2(IN) -I/O (io)

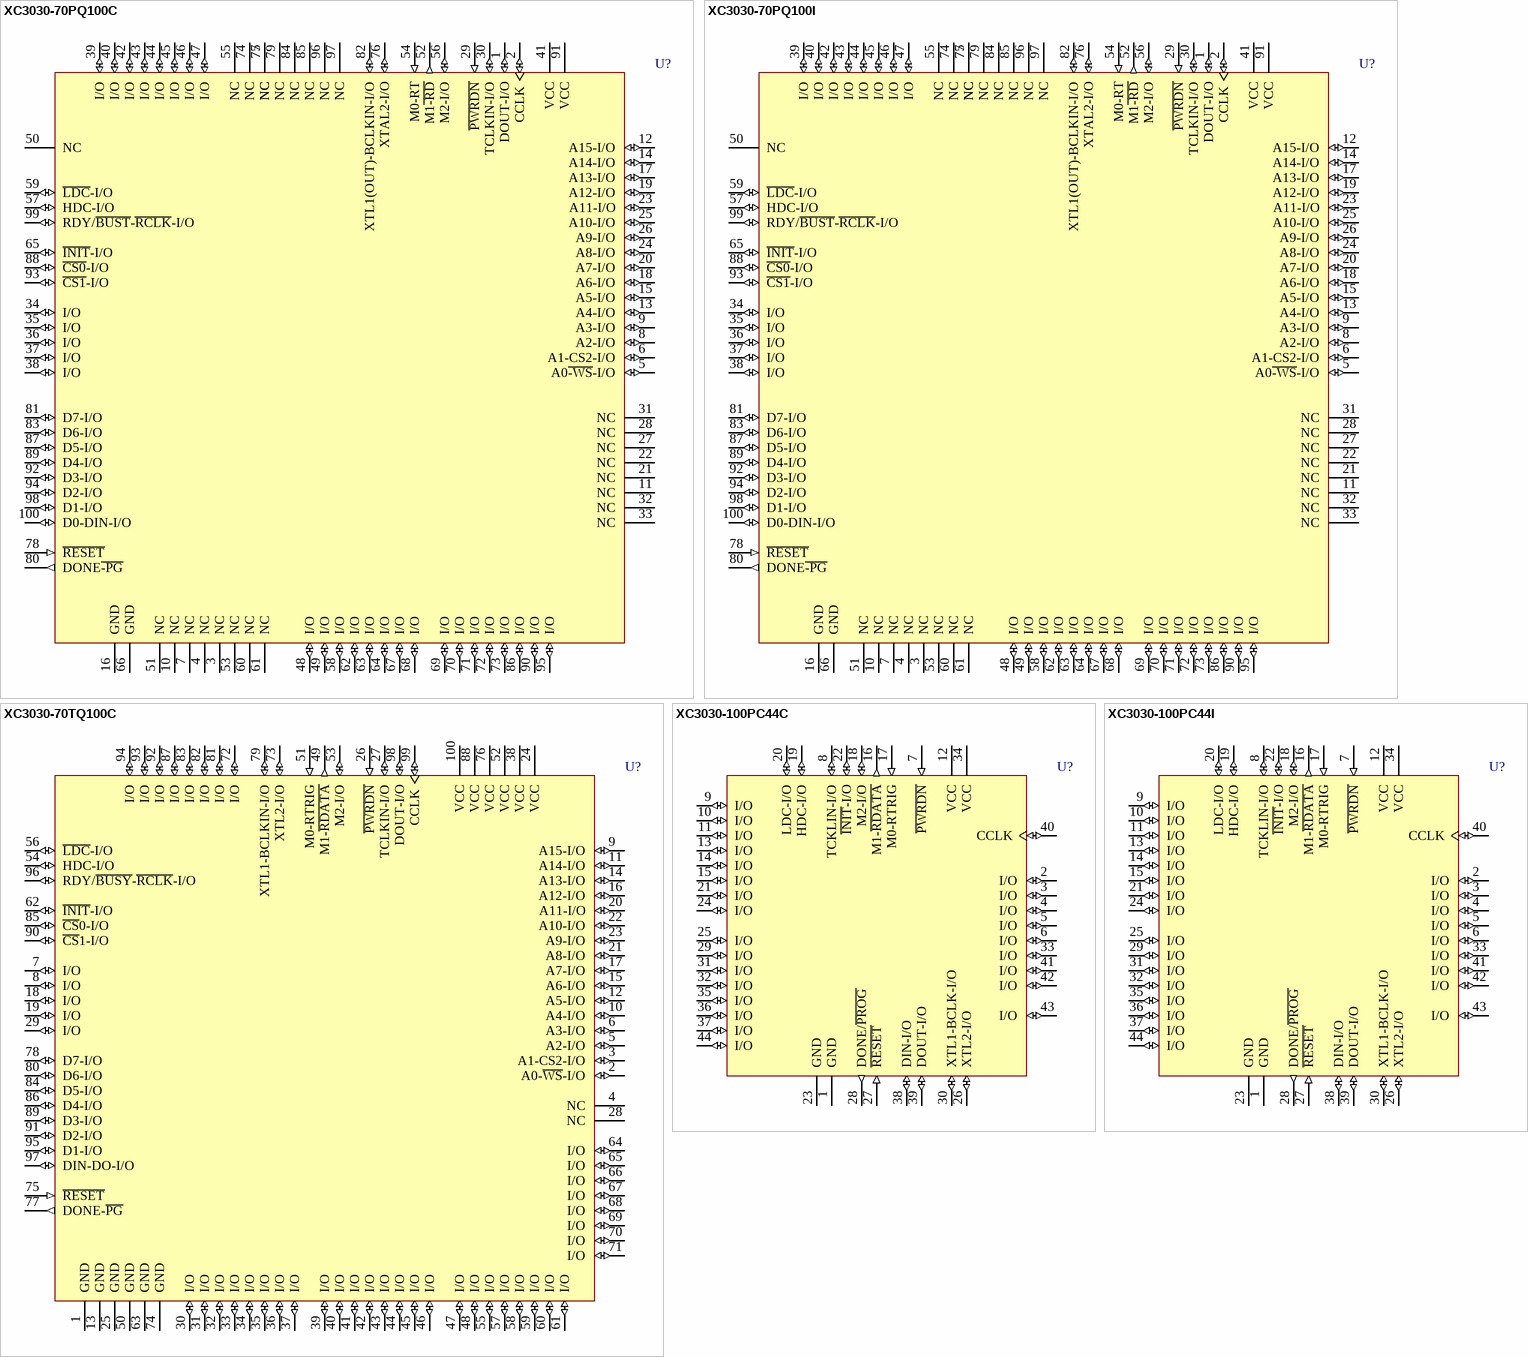
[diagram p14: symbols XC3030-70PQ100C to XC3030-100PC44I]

## XC3030-70PQ100C
designator U?
Logic Cell Array with 100 CLBs, with 64 I/O Pins, 100-Pin PQFP, Commercial Grade; ComponentAvailability: Not for New Design
footprint PQ100_N (QFP, 100-Leads, Body 20x14mm, Pitch 0.65mm, IPC Medium Density)
footprint PQ100_L (QFP, 100-Leads, Body 20x14mm, Pitch 0.65mm, IPC High Density)
footprint PQ100_M (QFP, 100-Leads, Body 20x14mm, Pitch 0.65mm, IPC Low Density)
3D model XC3030-PQ100 (100-Pin Plastic Quad Flat Pack (PQ100))
pins: 1 DOUT-I/O (io), 2 CCLK (io), 3 NC, 4 NC, 5 A0~{-WS}-I/O (io), 6 A1-CS2-I/O (io), 7 NC, 8 A2-I/O (io), 9 A3-I/O (io), 10 NC, 11 NC, 12 A15-I/O (io), 13 A4-I/O (io), 14 A14-I/O (io), 15 A5-I/O (io), 16 GND (power), 17 A13-I/O (io), 18 A6-I/O (io), 19 A12-I/O (io), 20 A7-I/O (io), 21 NC, 22 NC, 23 A11-I/O (io), 24 A8-I/O (io), 25 A10-I/O (io), 26 A9-I/O (io), 27 NC, 28 NC, 29 ~{PWRDN} (in), 30 TCLKIN-I/O (io), 31 NC, 32 NC, 33 NC, 34 I/O (io), 35 I/O (io), 36 I/O (io), 37 I/O (io), 38 I/O (io), 39 I/O (io), 40 I/O (io), 41 VCC (power), 42 I/O (io), 43 I/O (io), 44 I/O (io), 45 I/O (io), 46 I/O (io), 47 I/O (io), 48 I/O (io), 49 I/O (io), 50 NC, 51 NC, 52 M1~{-RD} (out), 53 NC, 54 M0-RT (in), 55 NC, 56 M2-I/O (io), 57 HDC-I/O (io), 58 I/O (io), 59 ~{LDC}-I/O (io), 60 NC, 61 NC, 62 I/O (io), 63 I/O (io), 64 I/O (io), 65 ~{INIT}-I/O (io), 66 GND (power), 67 I/O (io), 68 I/O (io), 69 I/O (io), 70 I/O (io), 71 I/O (io), 72 I/O (io), 73 I/O (io), 74 NC, 75 NC, 76 XTAL2-I/O (io), 77 NC, 78 ~{RESET} (in), 79 NC, 80 DONE~{-PG} (out), 81 D7-I/O (io), 82 XTL1(OUT)-BCLKIN-I/O (io), 83 D6-I/O (io), 84 NC, 85 NC, 86 I/O (io), 87 D5-I/O (io), 88 ~{CS0}-I/O (io), 89 D4-I/O (io), 90 I/O (io), 91 VCC (power), 92 D3-I/O (io), 93 ~{CS1}-I/O (io), 94 D2-I/O (io), 95 I/O (io), 96 NC, 97 NC, 98 D1-I/O (io), 99 RDY/~{BUST}-~{RCLK}-I/O (io), 100 D0-DIN-I/O (io)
